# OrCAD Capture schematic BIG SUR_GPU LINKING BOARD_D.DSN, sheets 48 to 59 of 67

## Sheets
48 P49  P12V_1 Hot Swap-2: size C
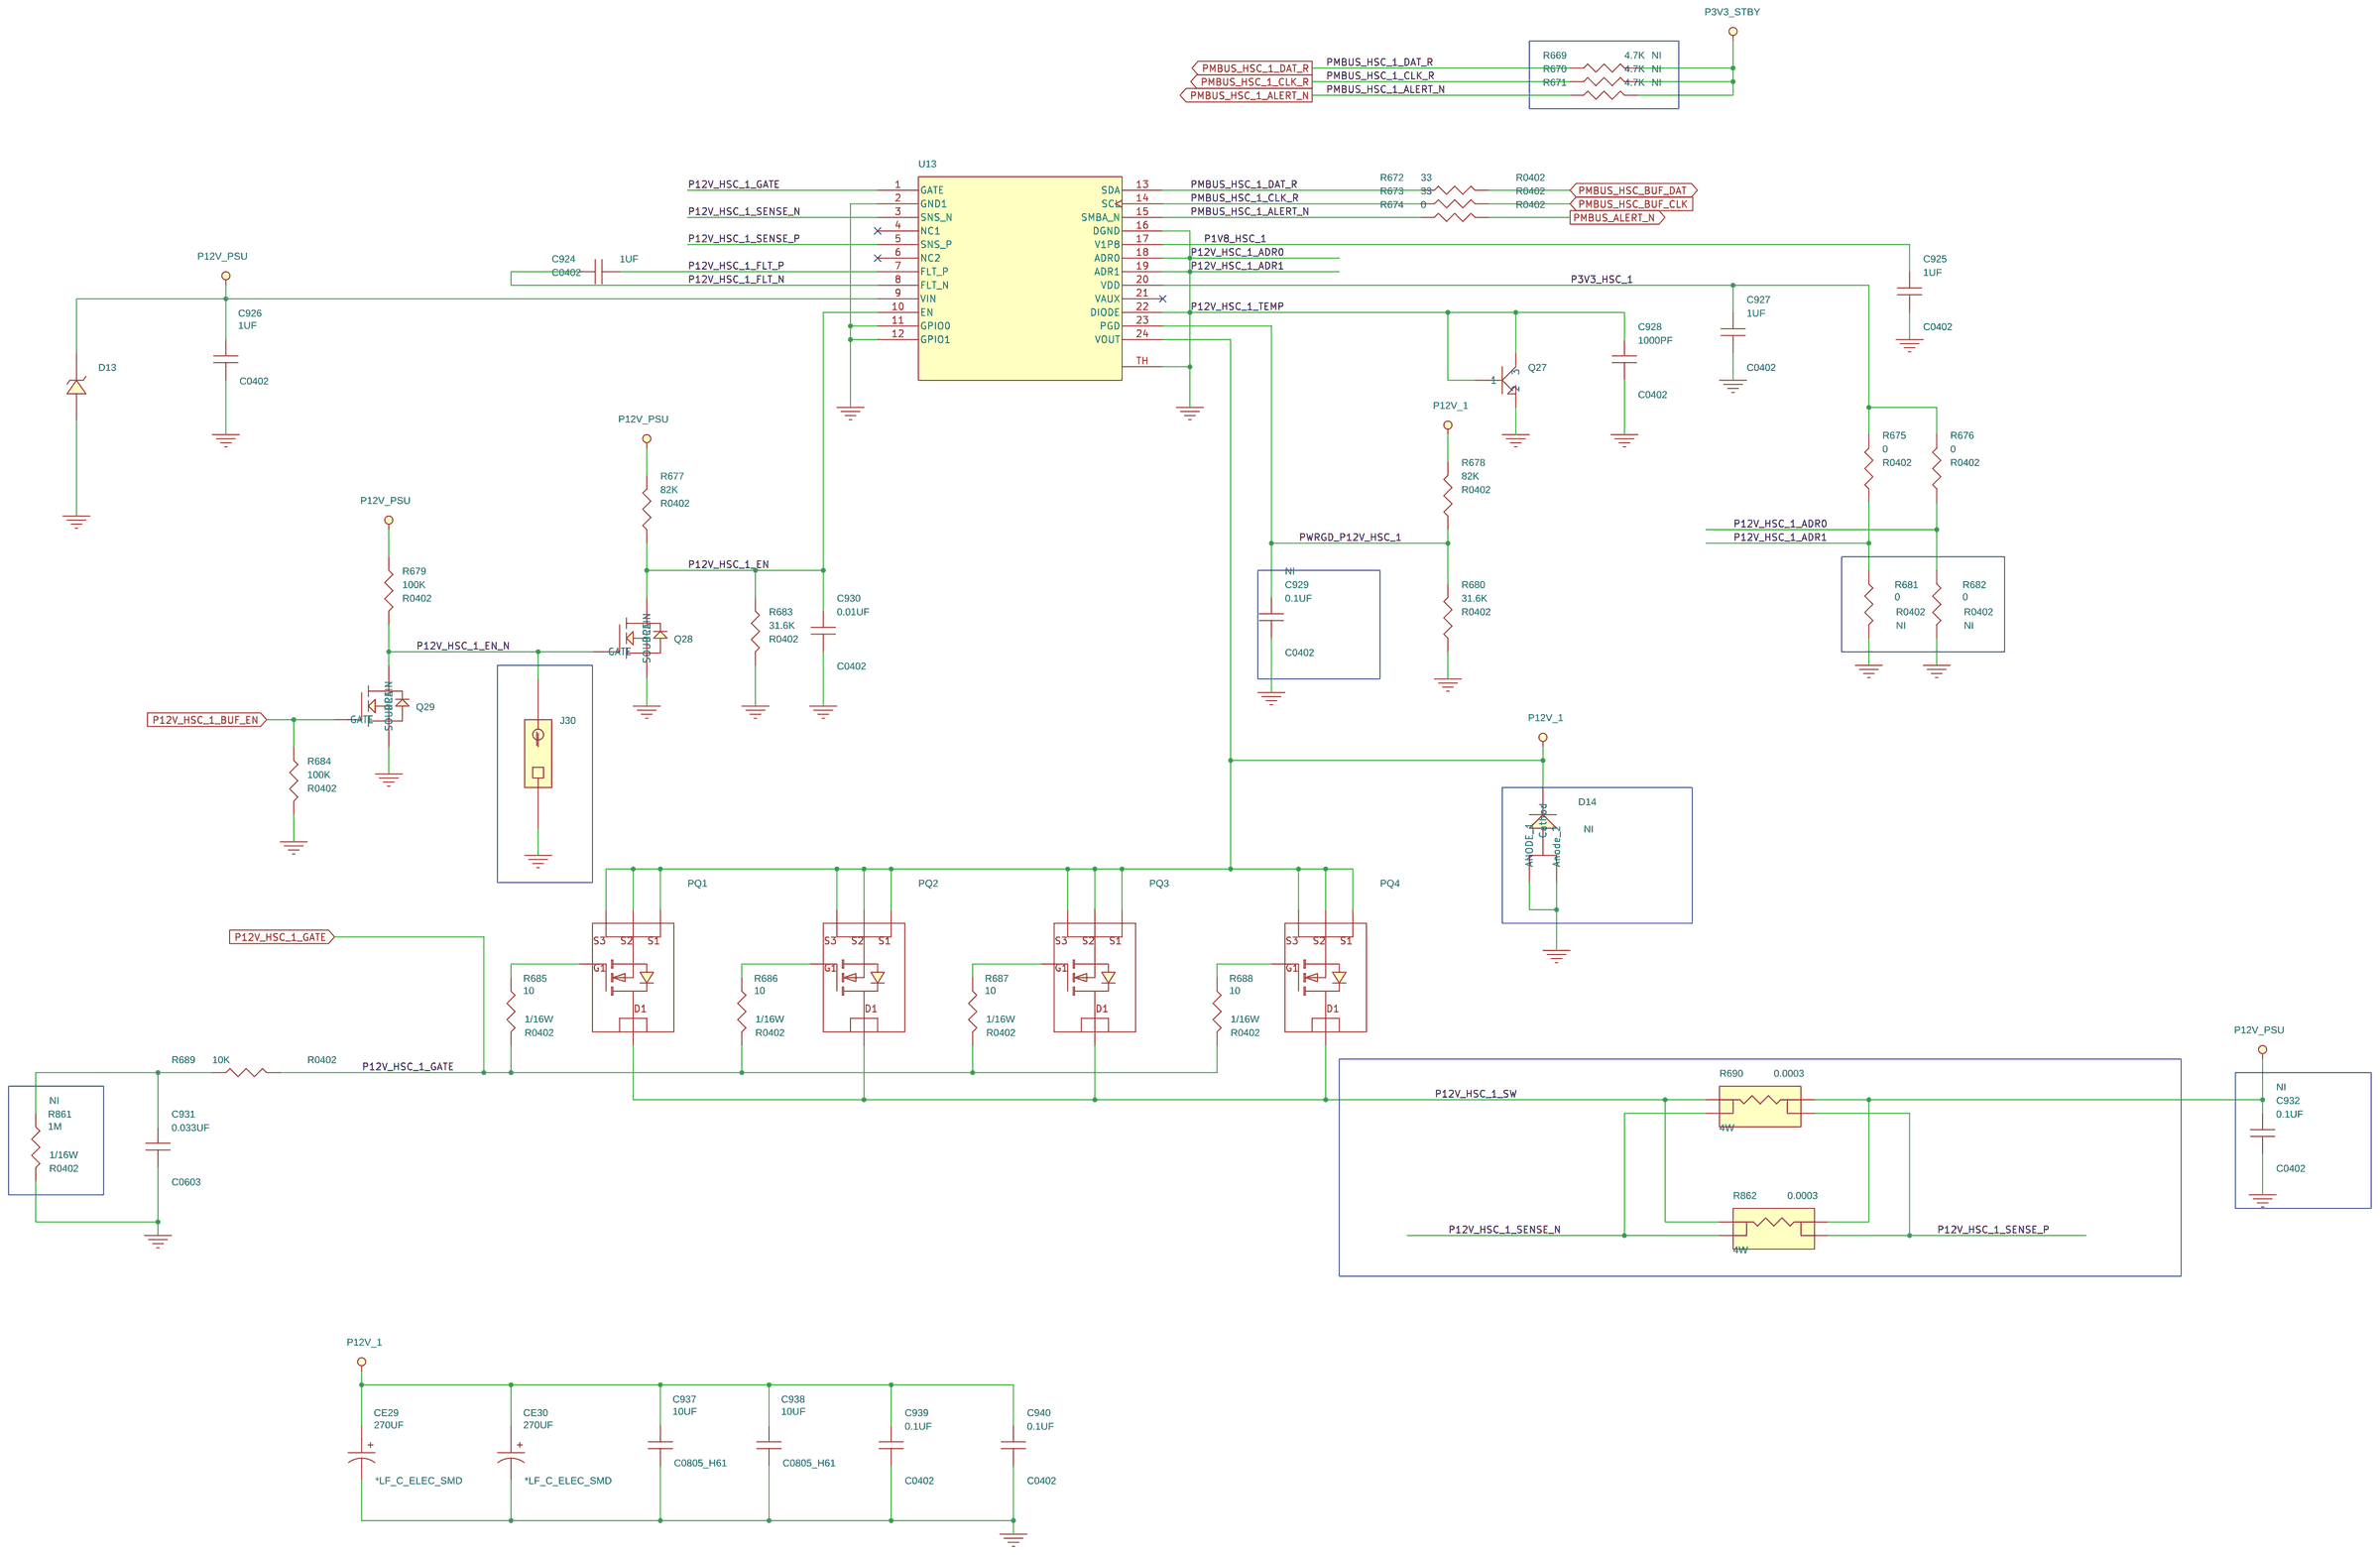
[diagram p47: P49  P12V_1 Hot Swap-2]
49 P50  P12V_2 Hot Swap-0: size C
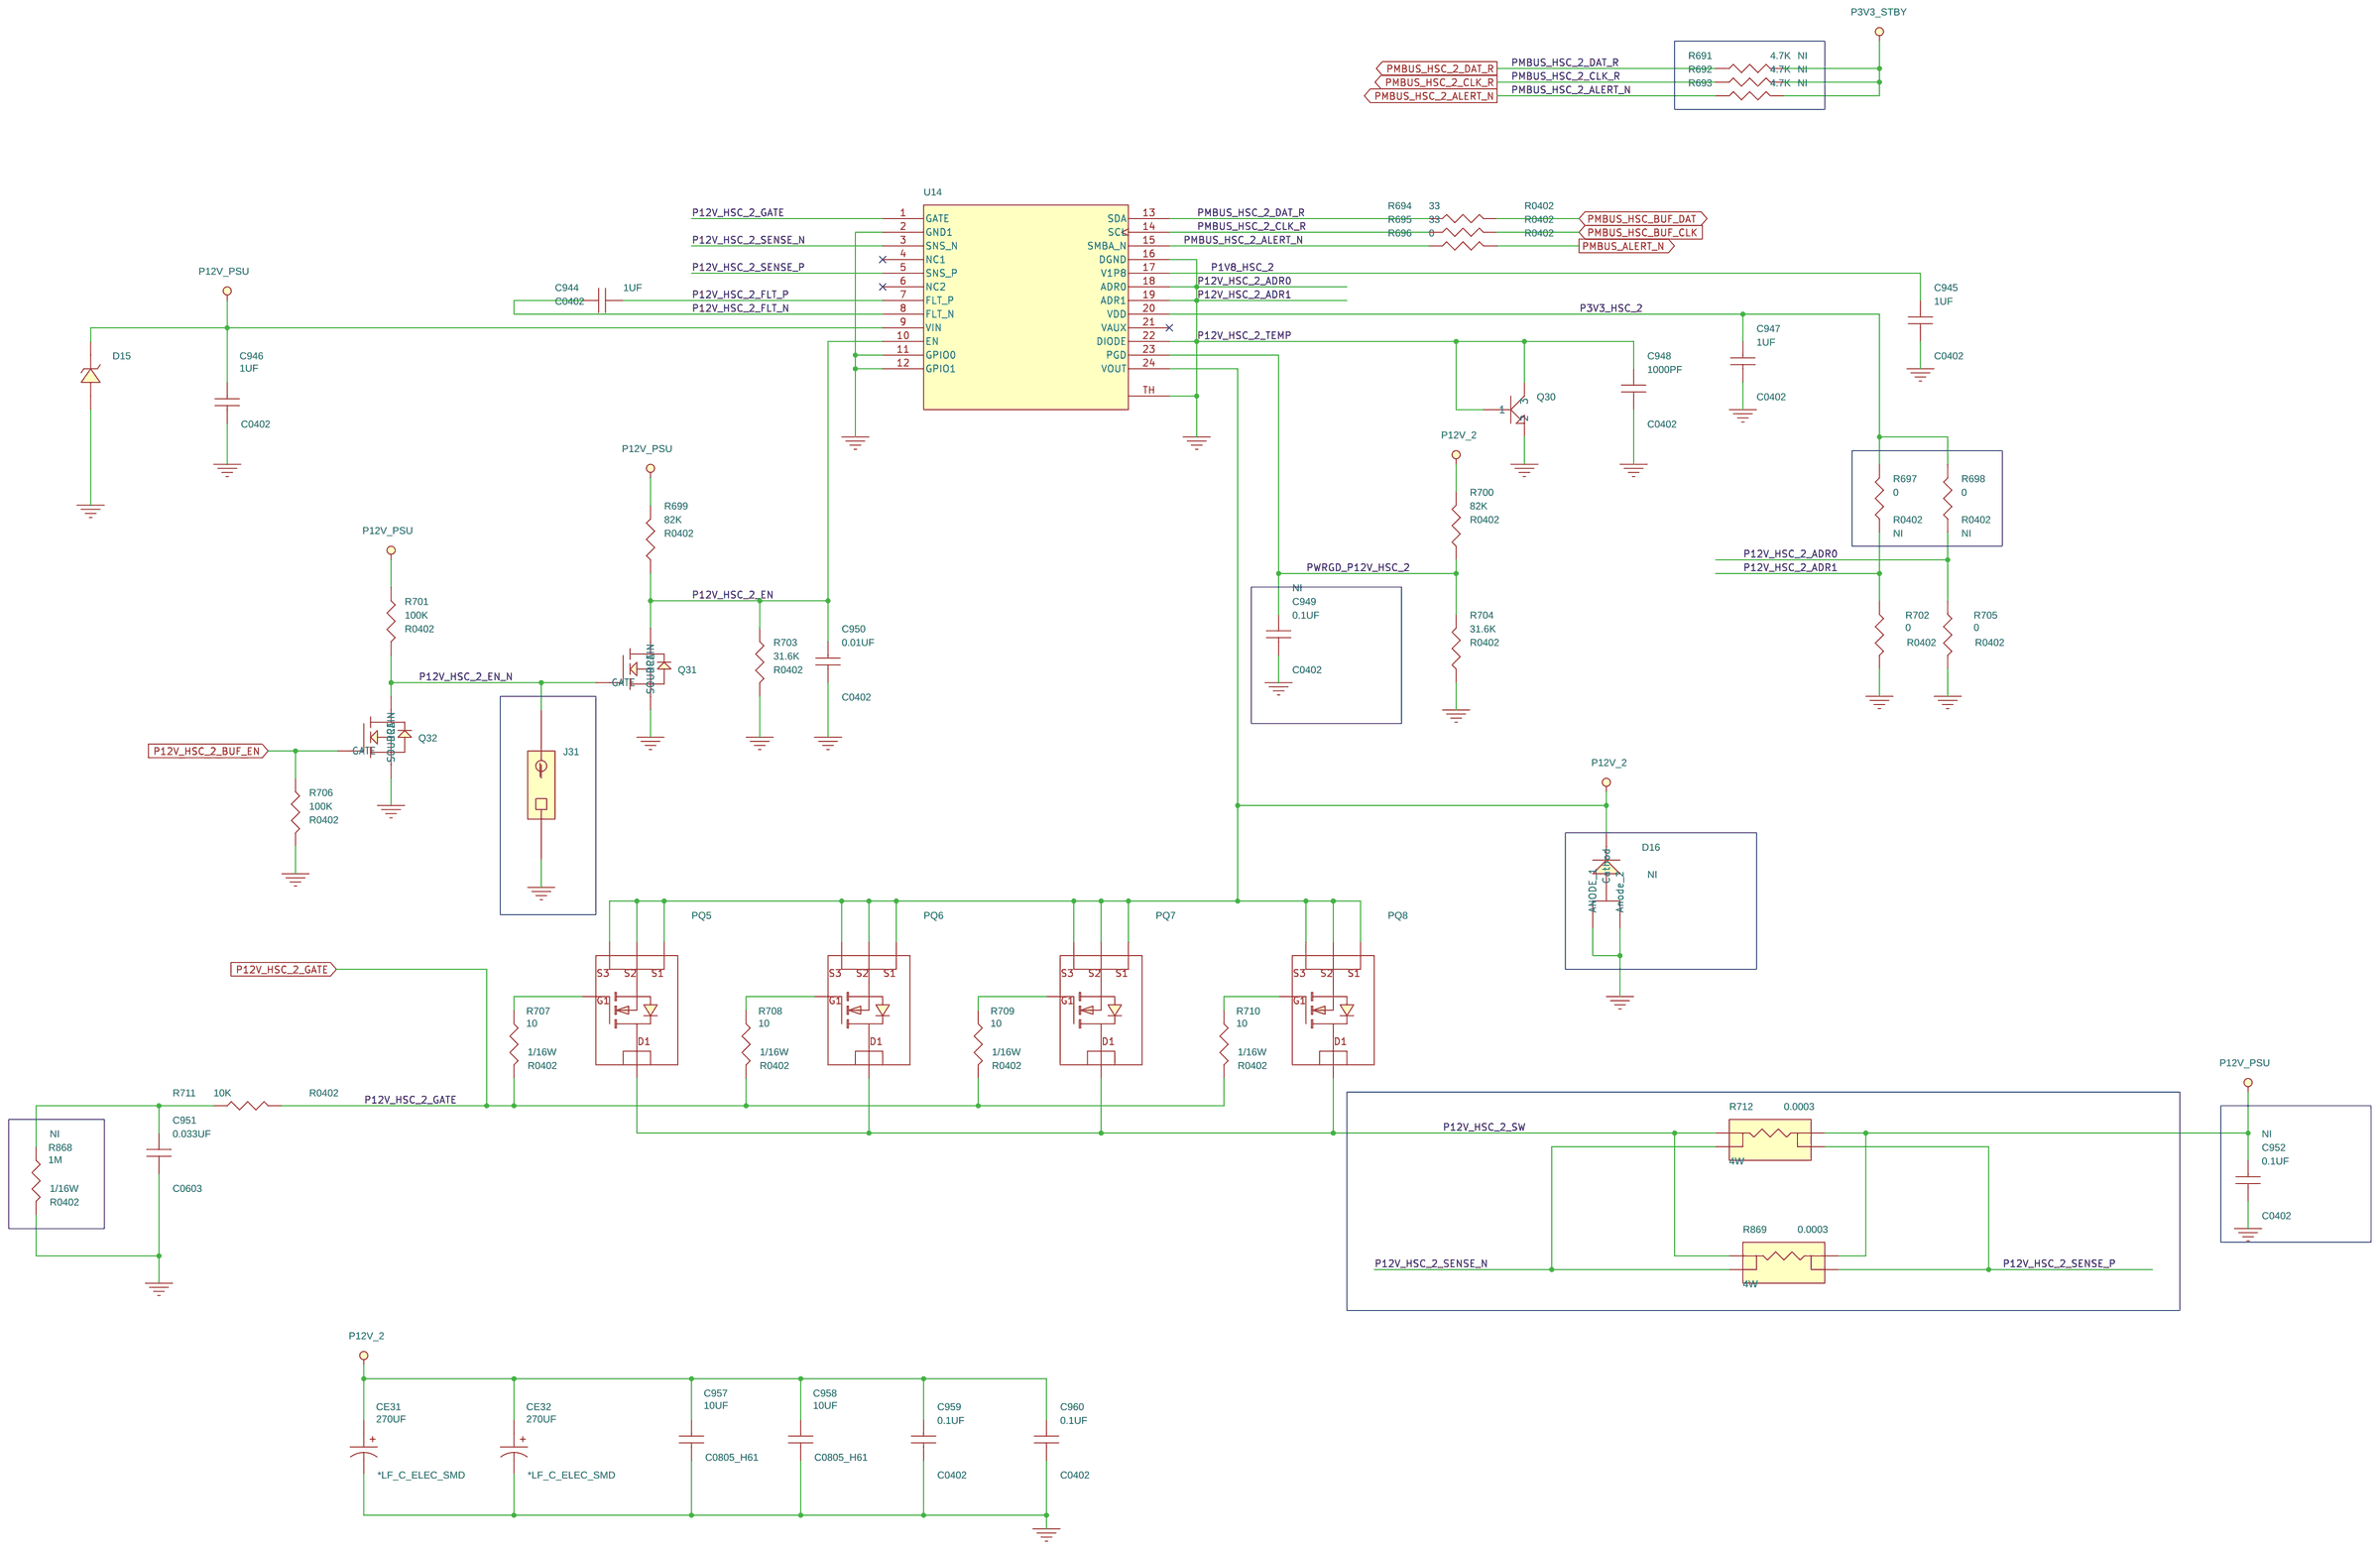
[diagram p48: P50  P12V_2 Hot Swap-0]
50 P51  P12V Hot Swap-1: size C
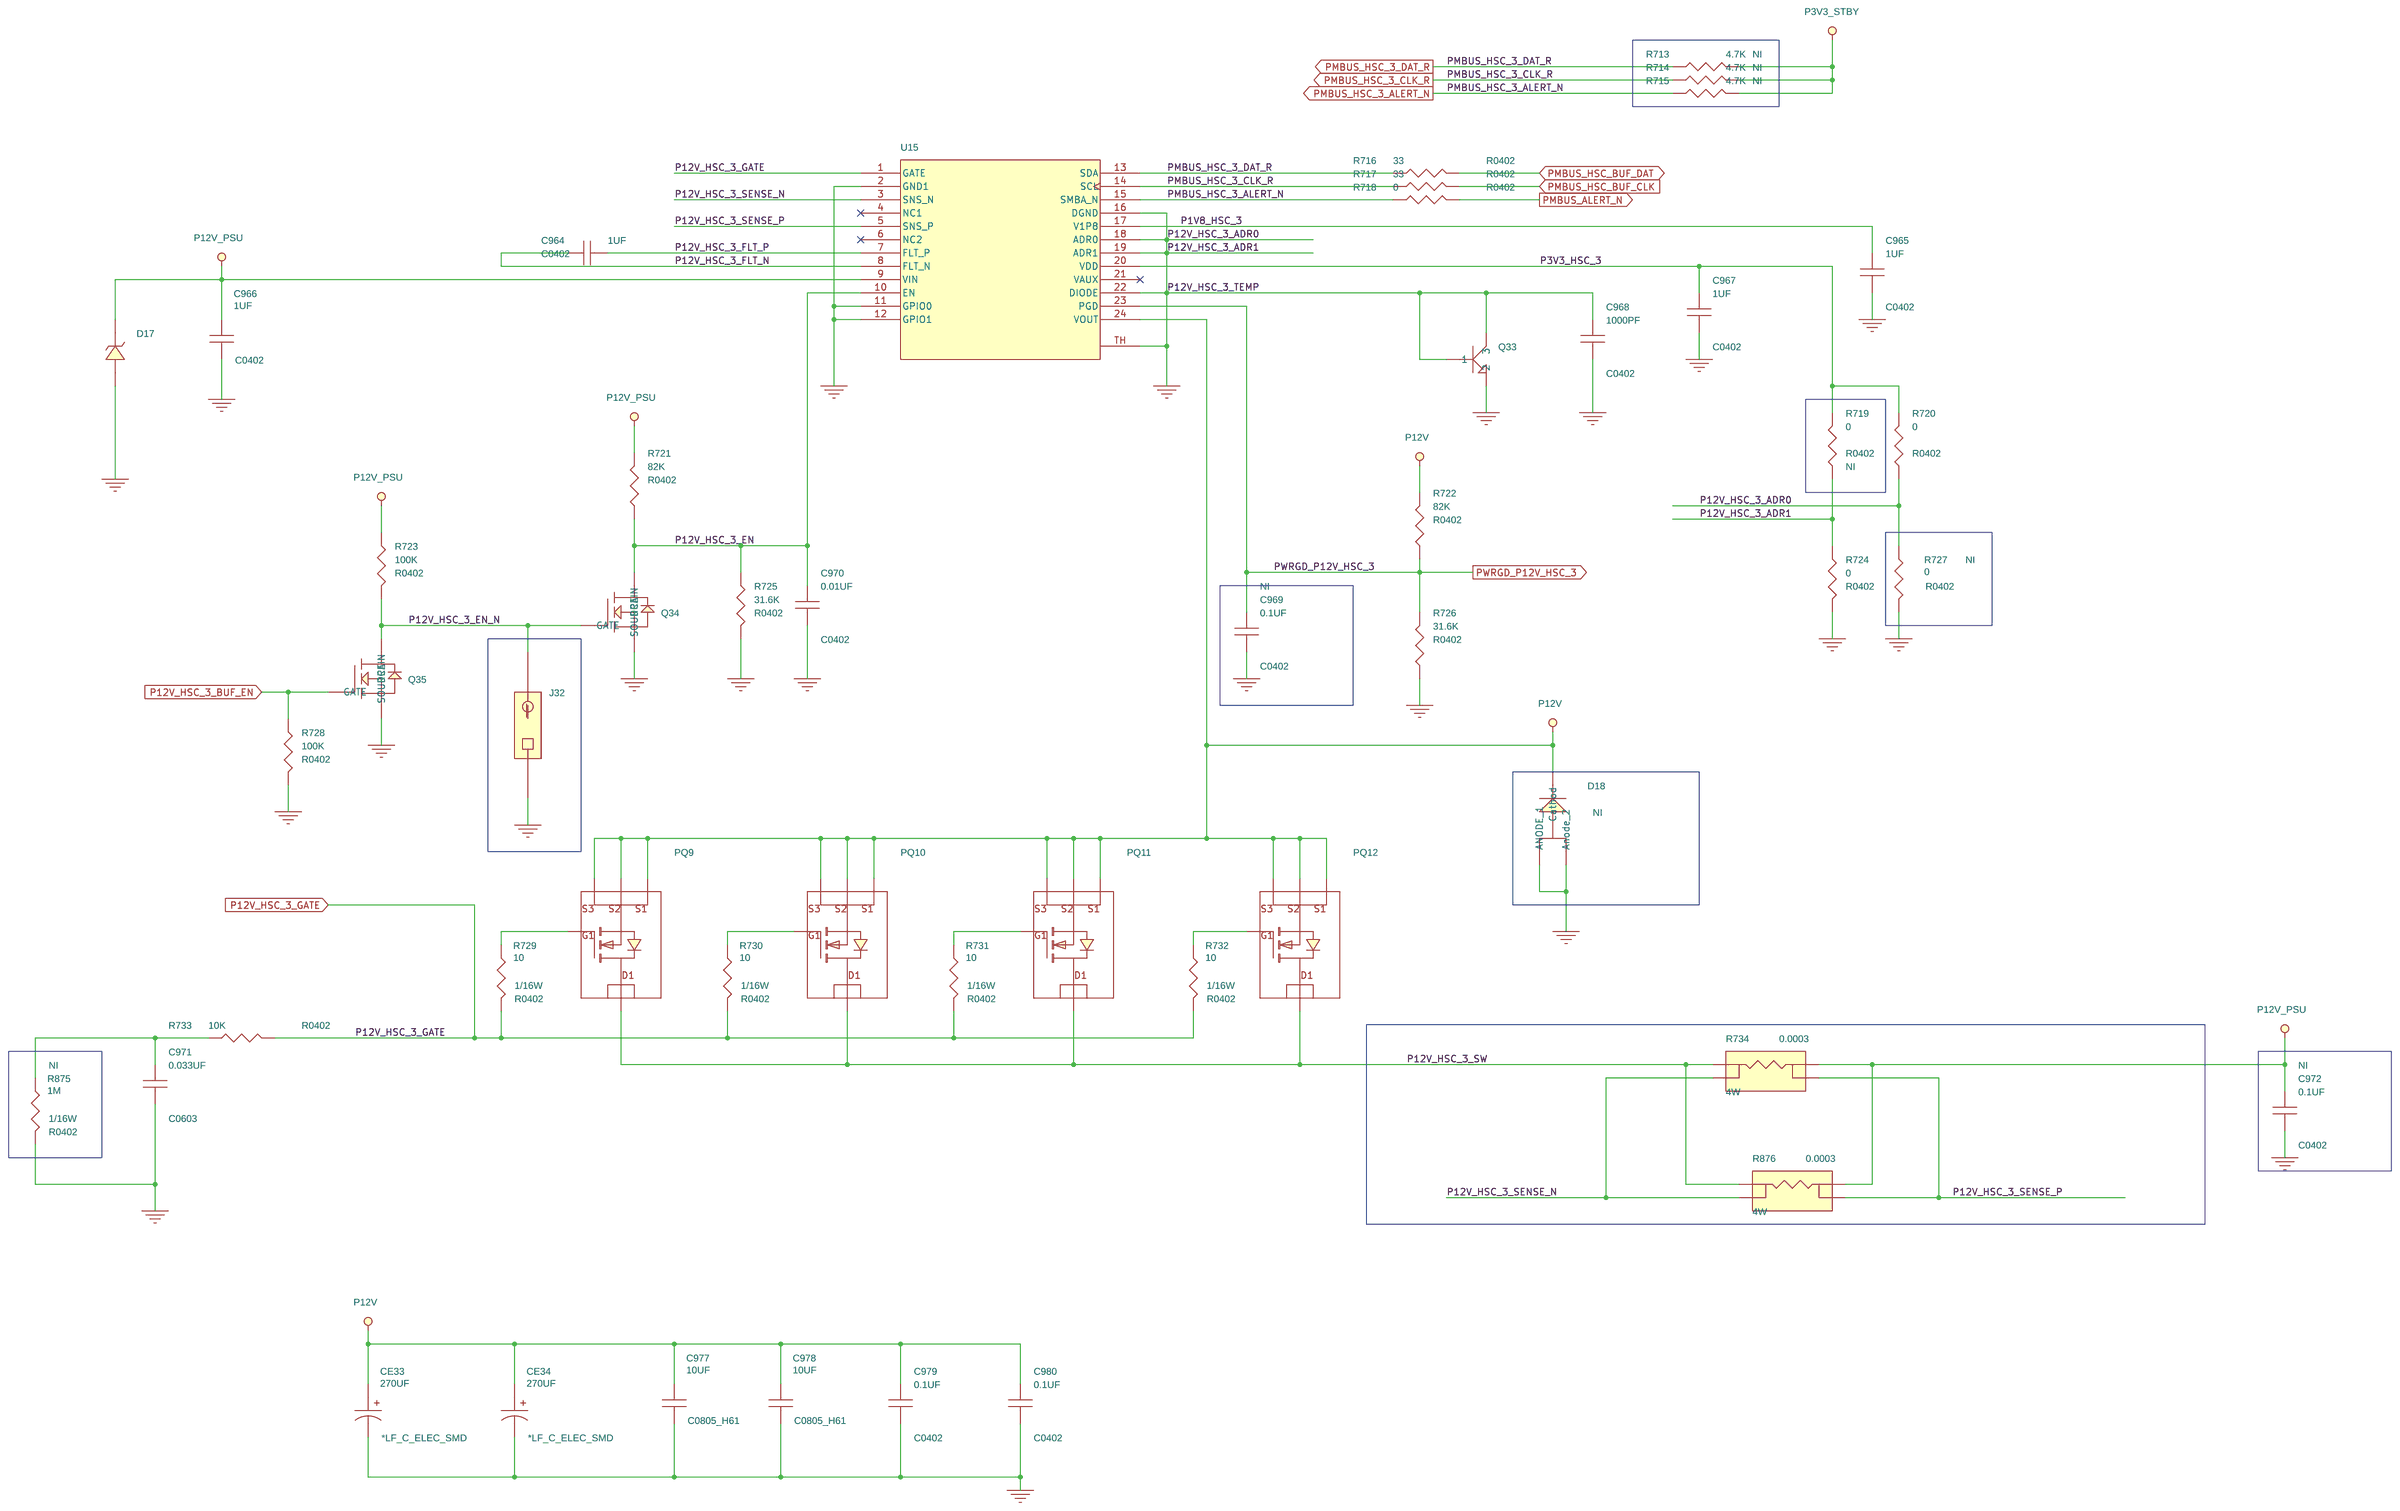
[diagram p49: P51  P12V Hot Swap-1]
51 P52  Hardware Monitor: size C
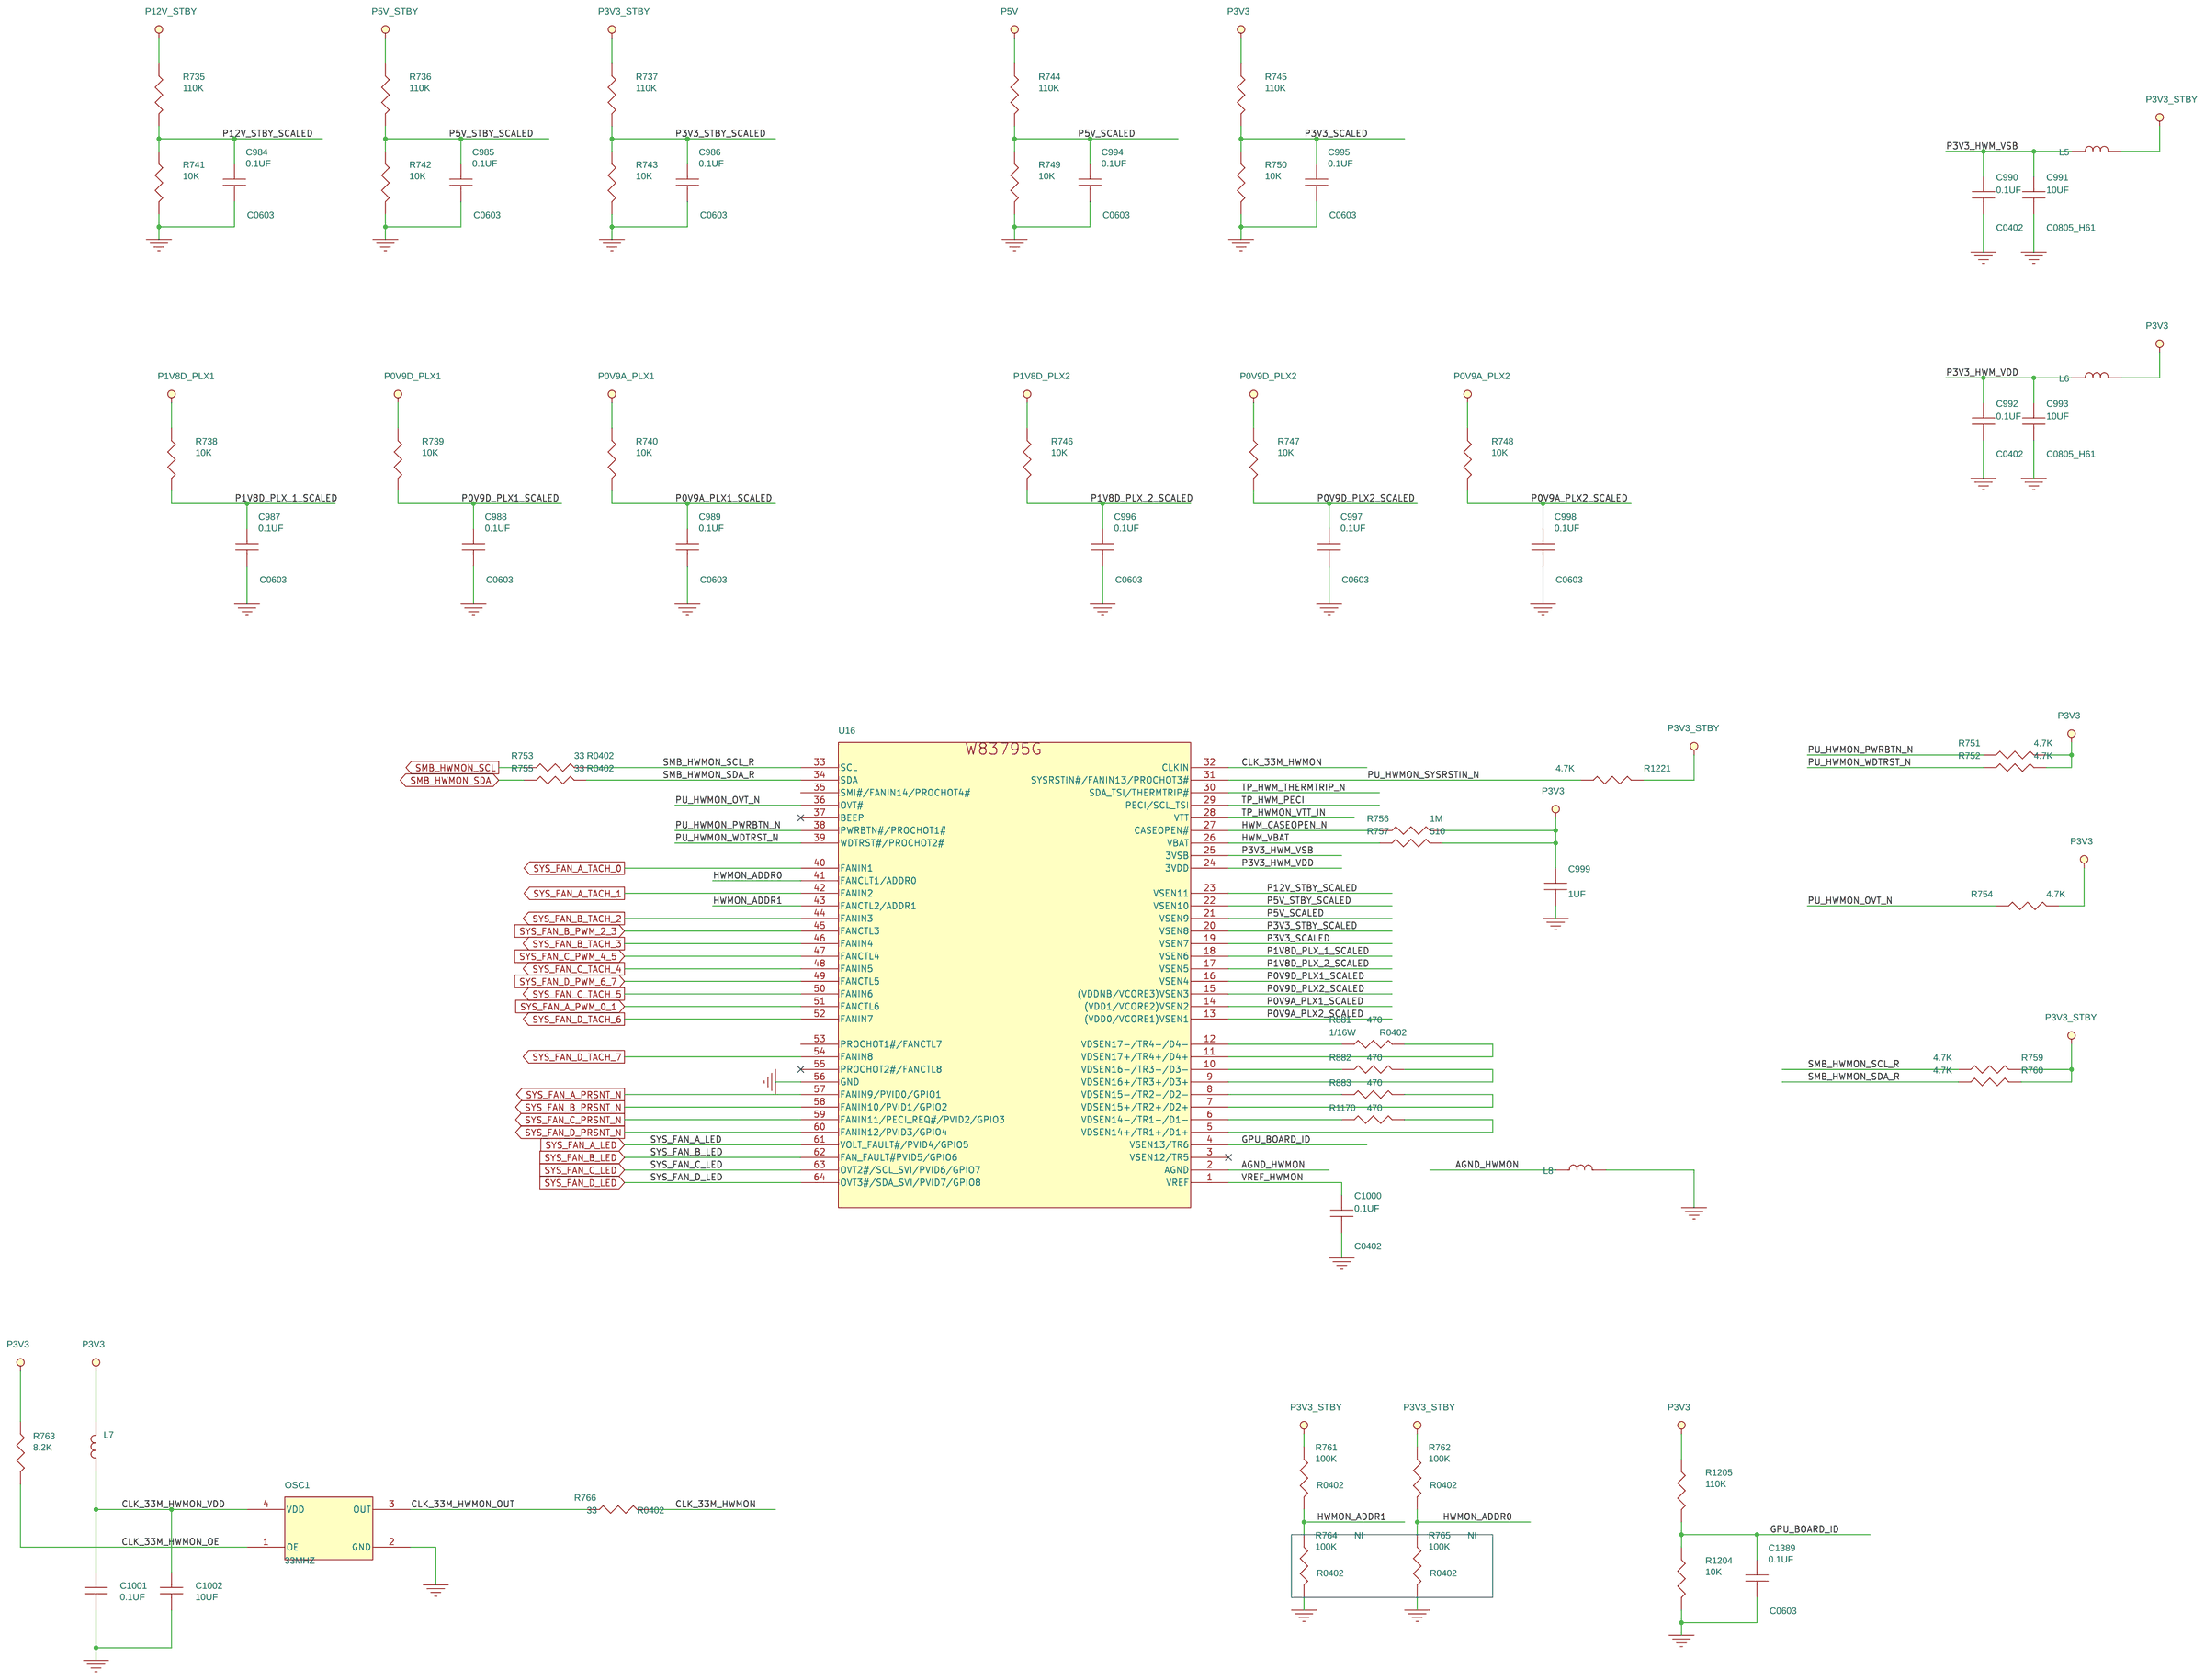
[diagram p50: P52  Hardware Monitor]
52 P53 Sytem Fan Module Connector: size C
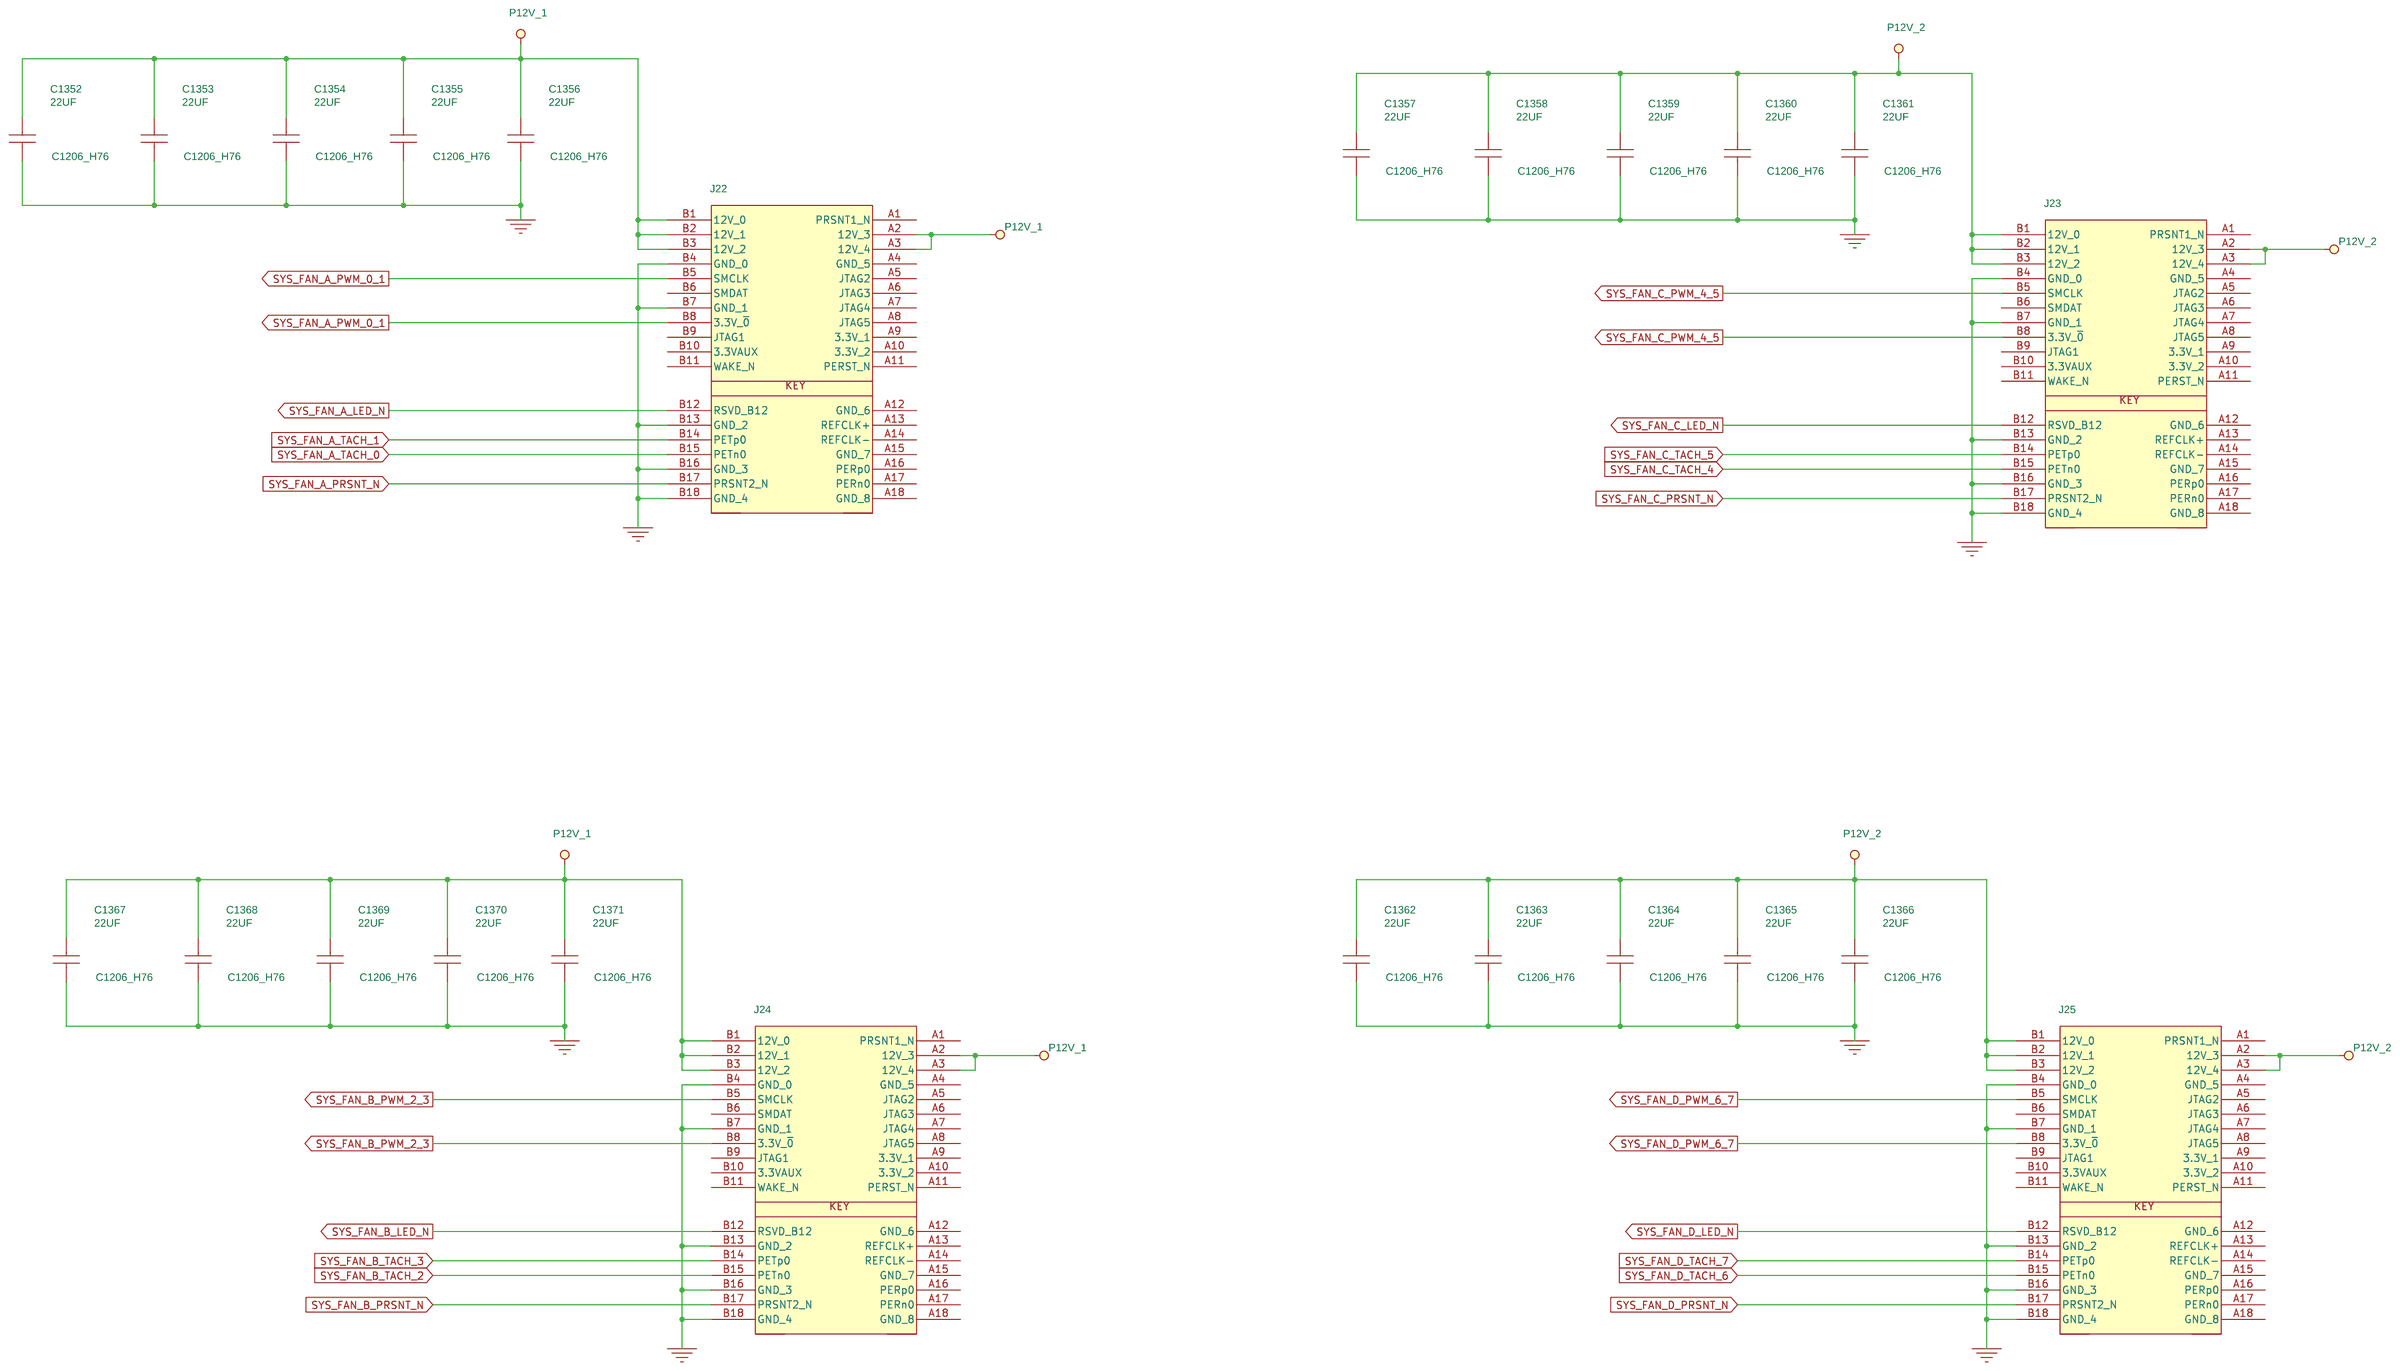
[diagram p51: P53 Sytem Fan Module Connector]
53 P54  Sytem Fan Module: size C
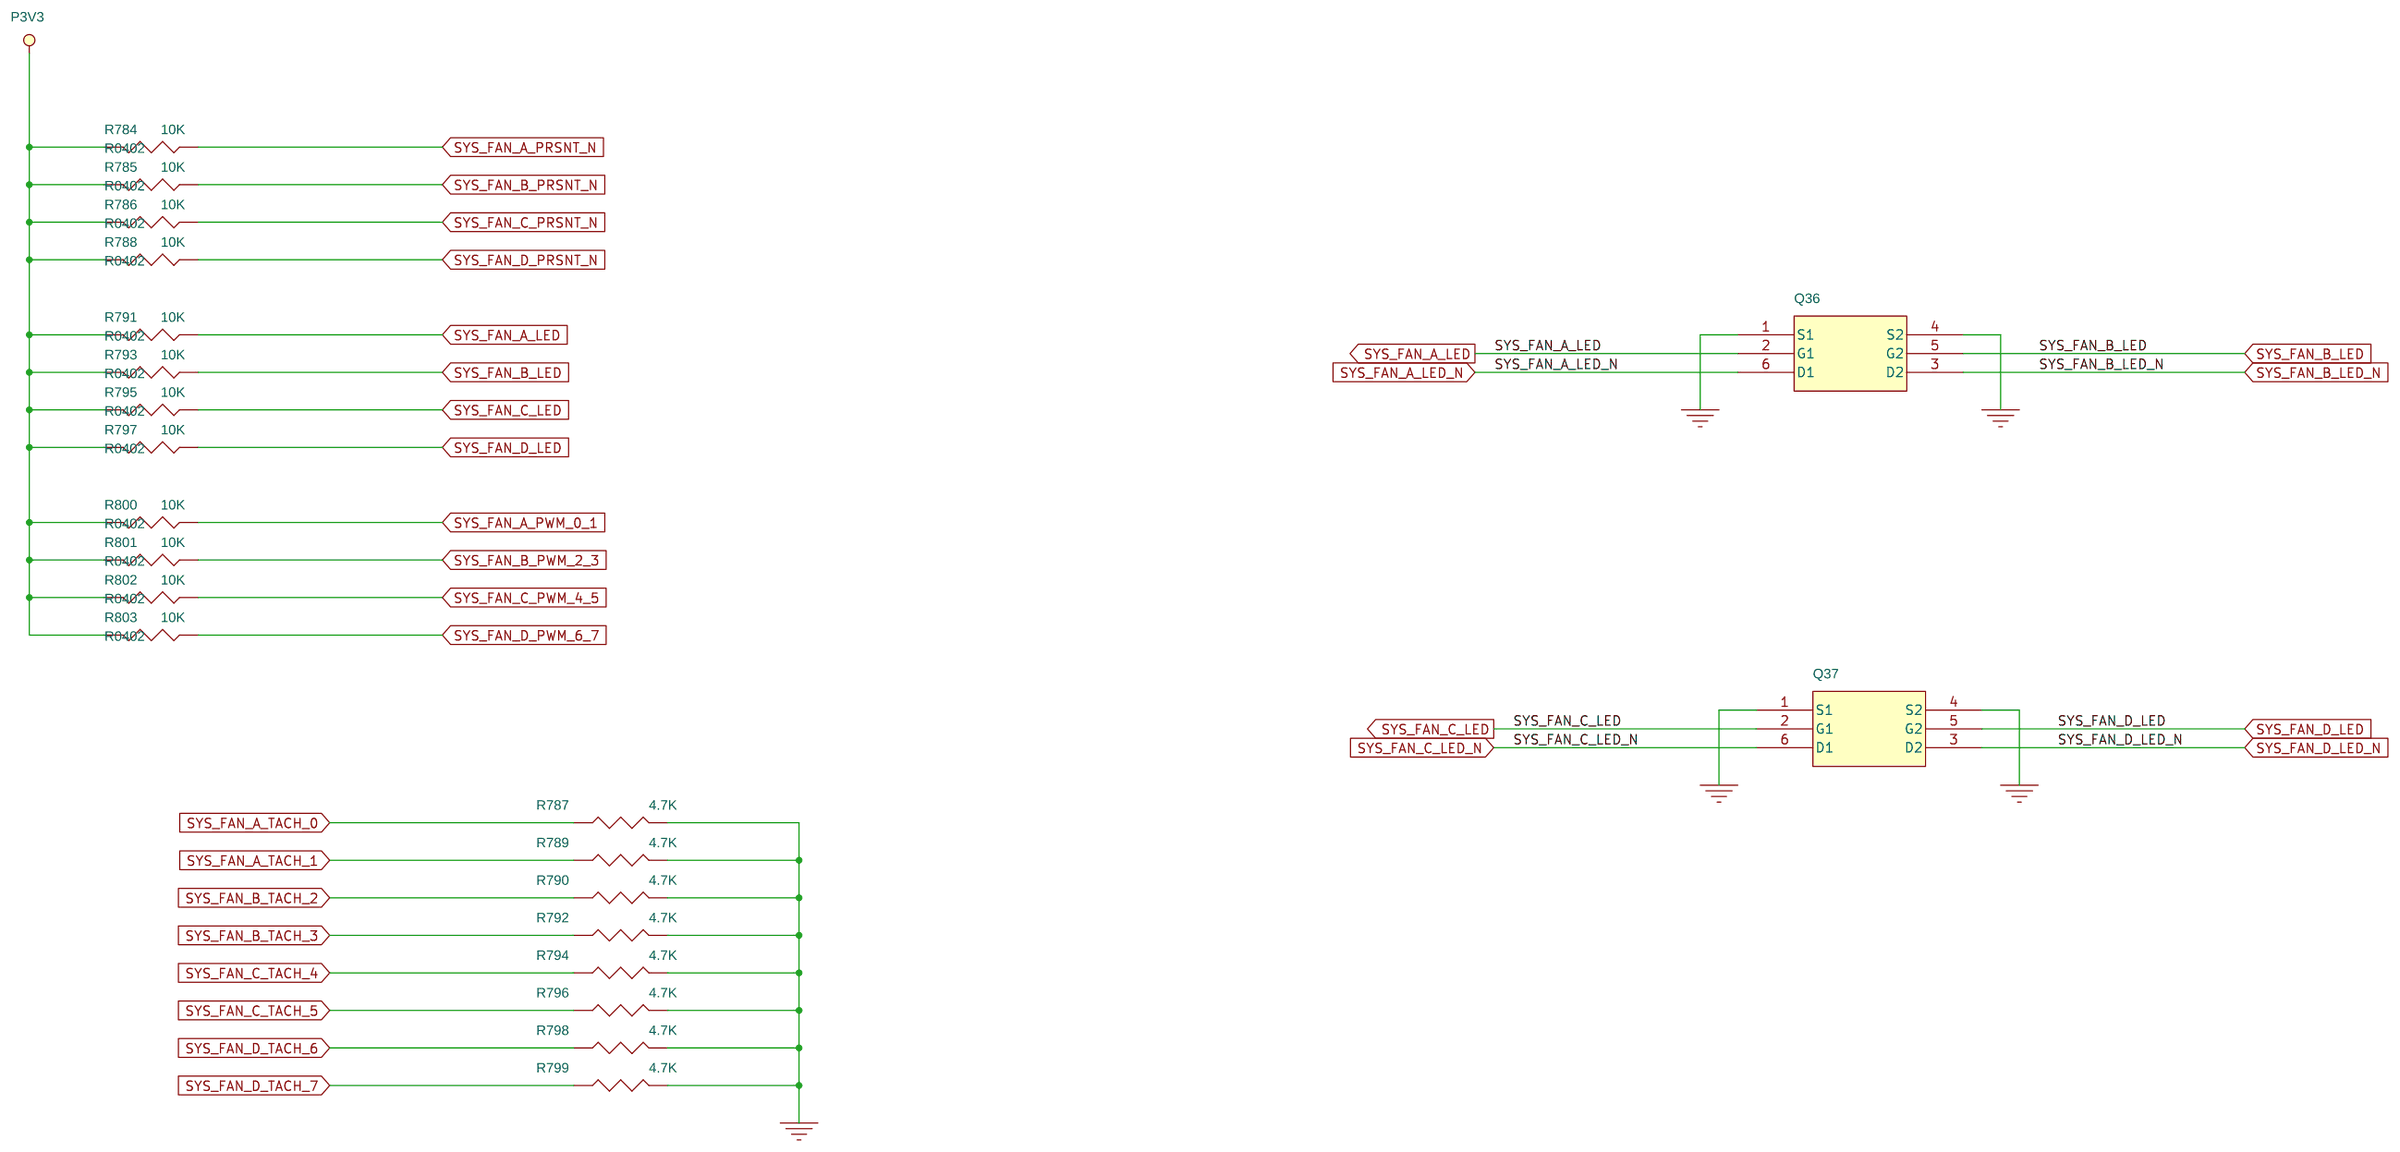
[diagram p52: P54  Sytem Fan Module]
54 P56  Reset Control Circuit-1: size Custom
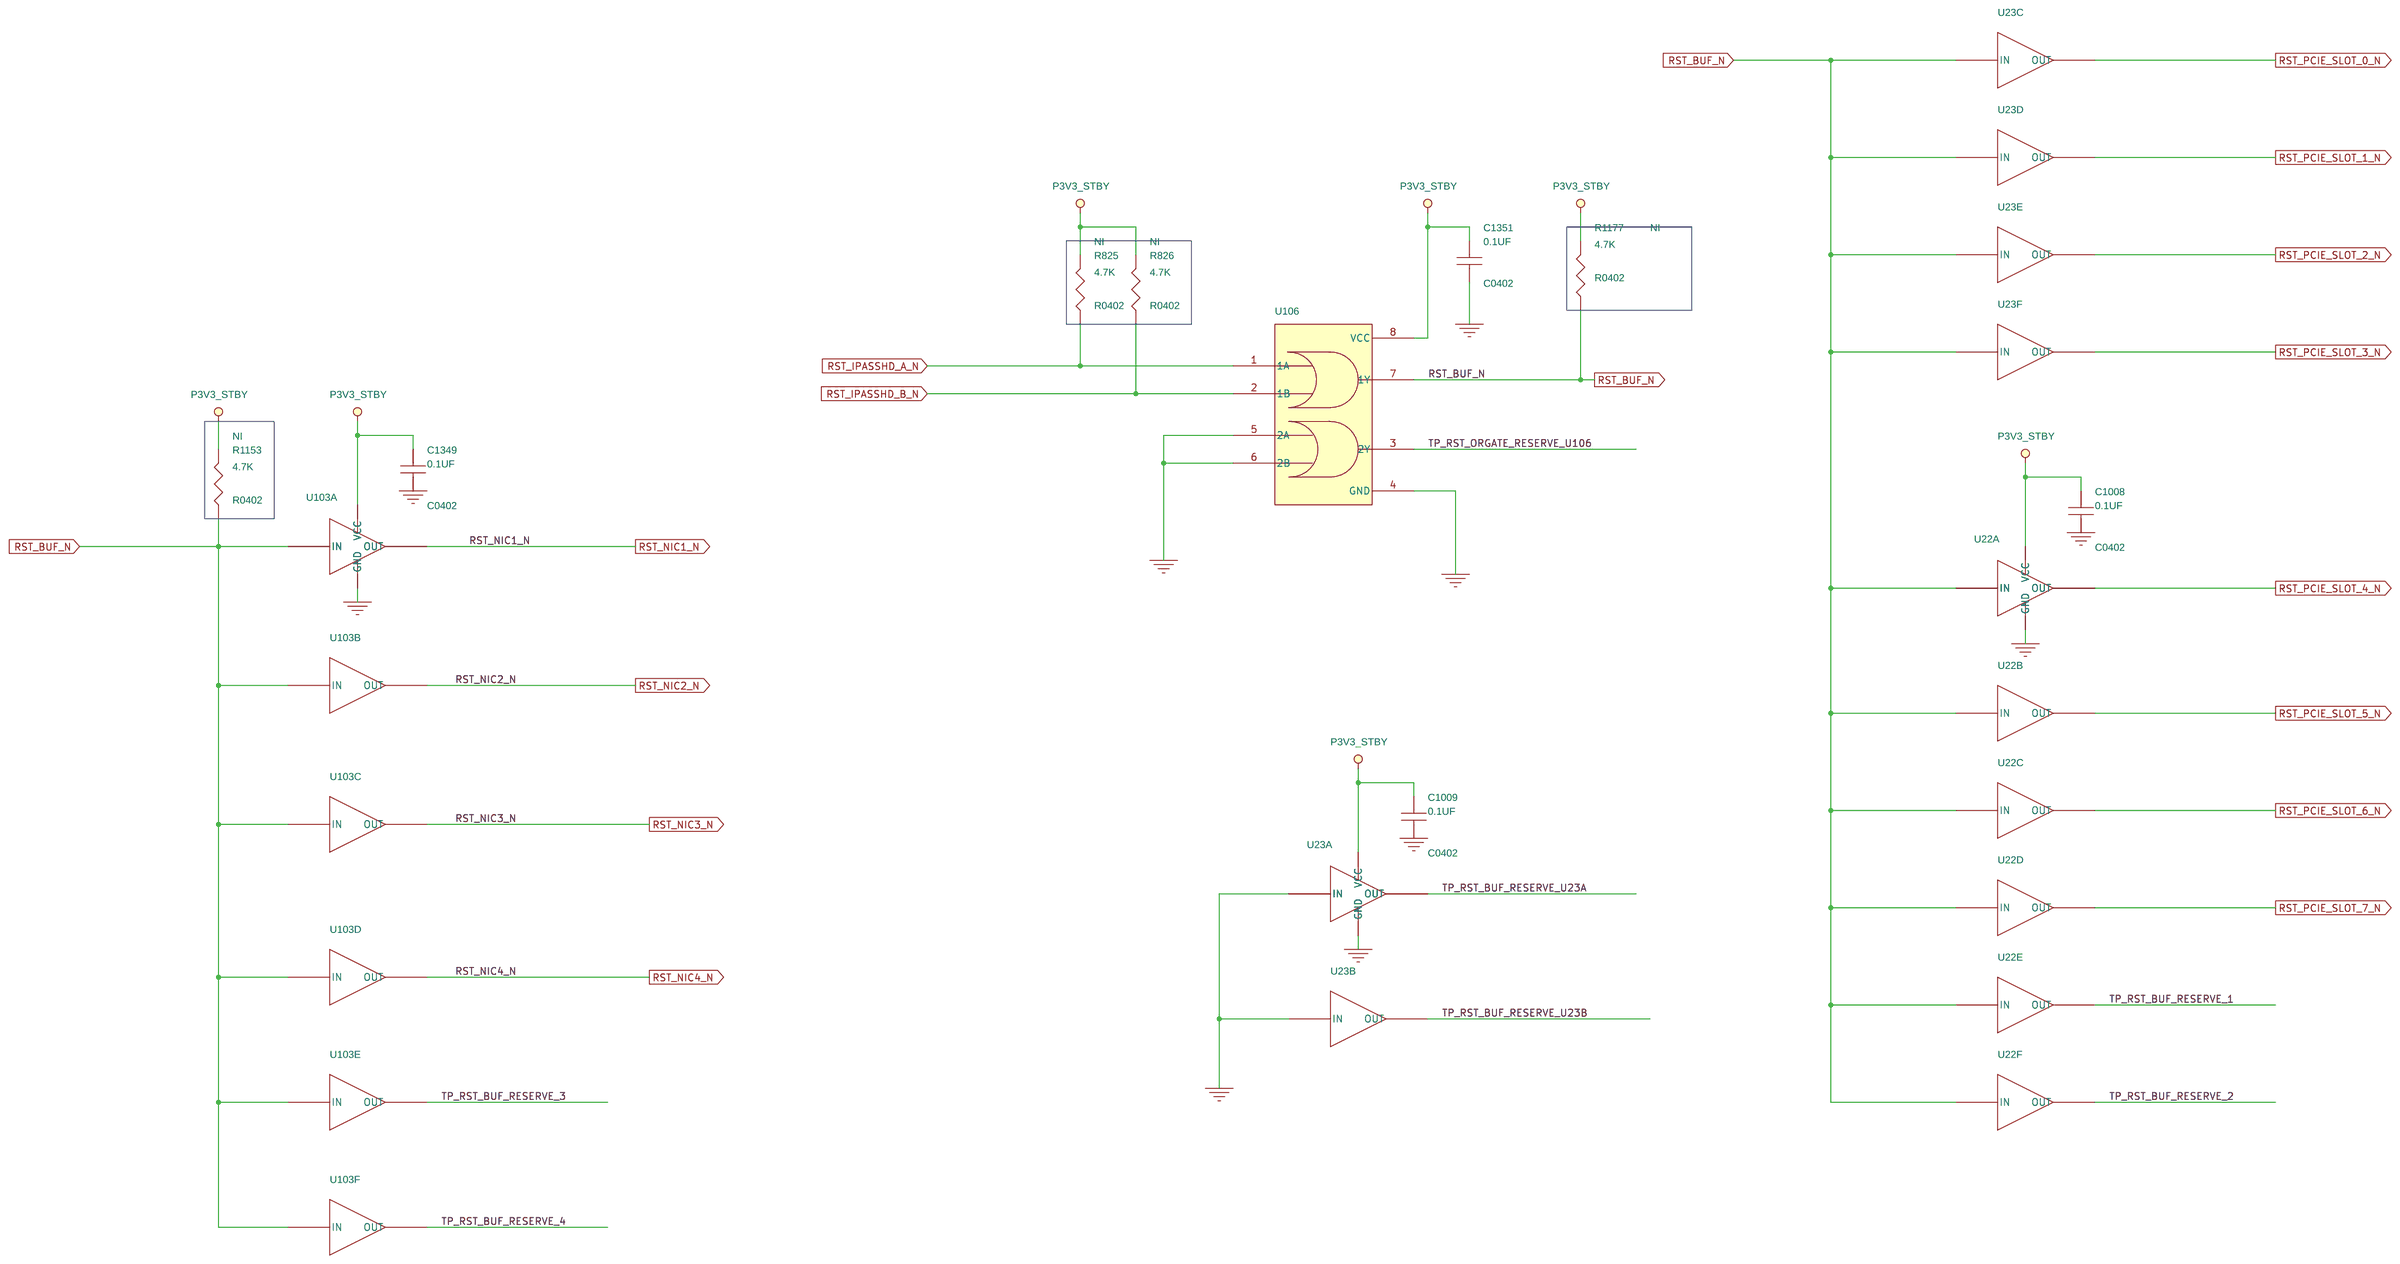
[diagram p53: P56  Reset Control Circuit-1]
55 P57  Reset Control Circuit-2: size Custom
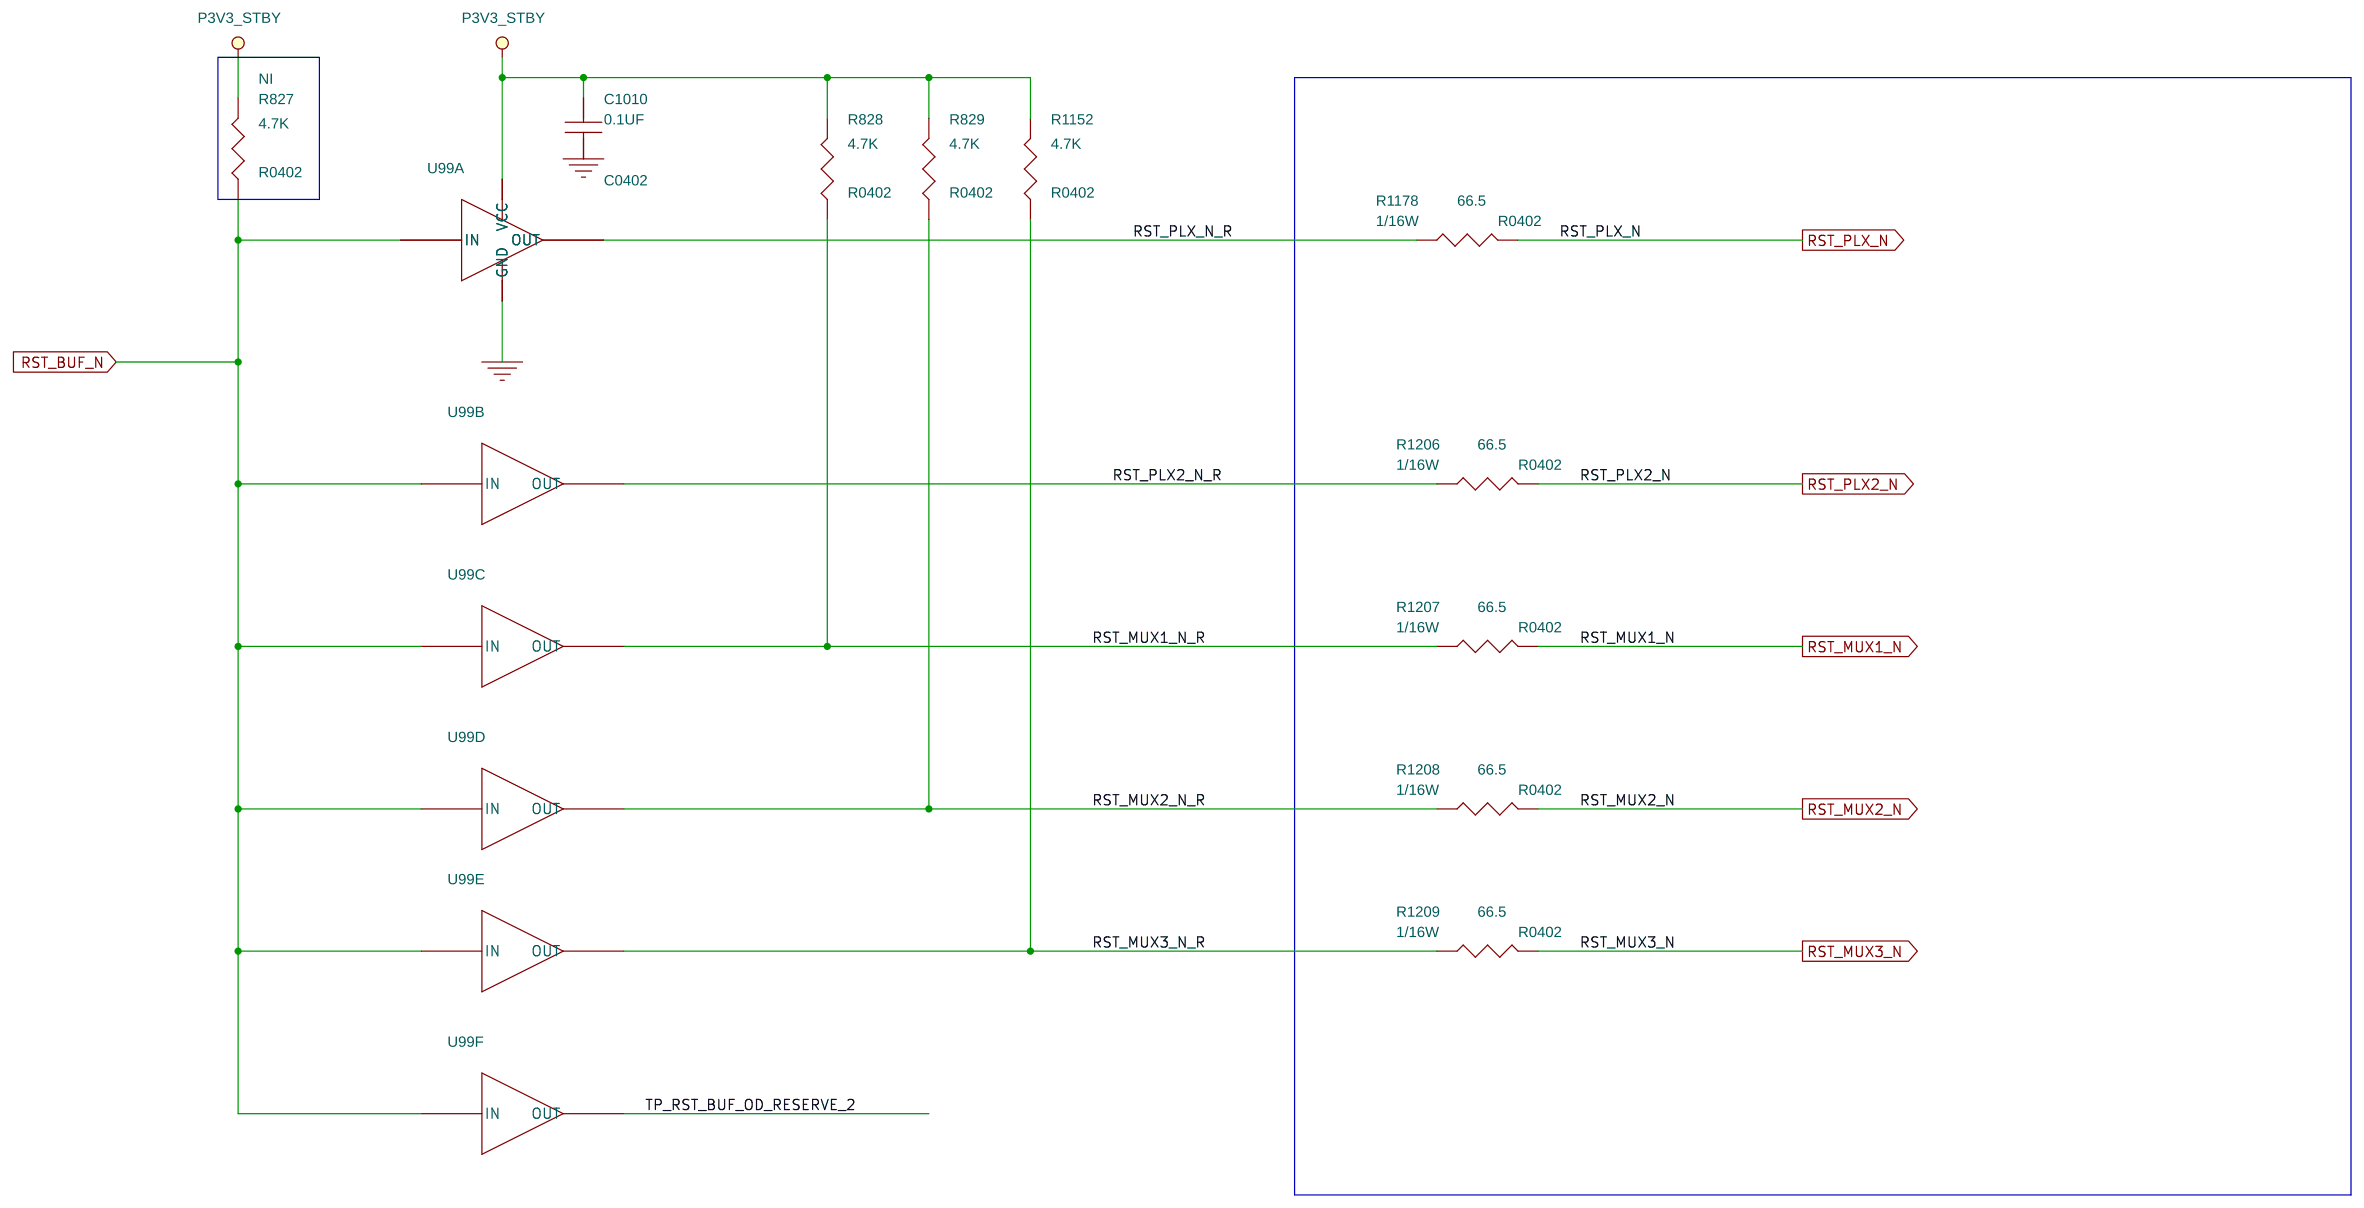
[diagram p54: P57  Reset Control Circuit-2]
56 P58  P5V_STBY VR: size Custom
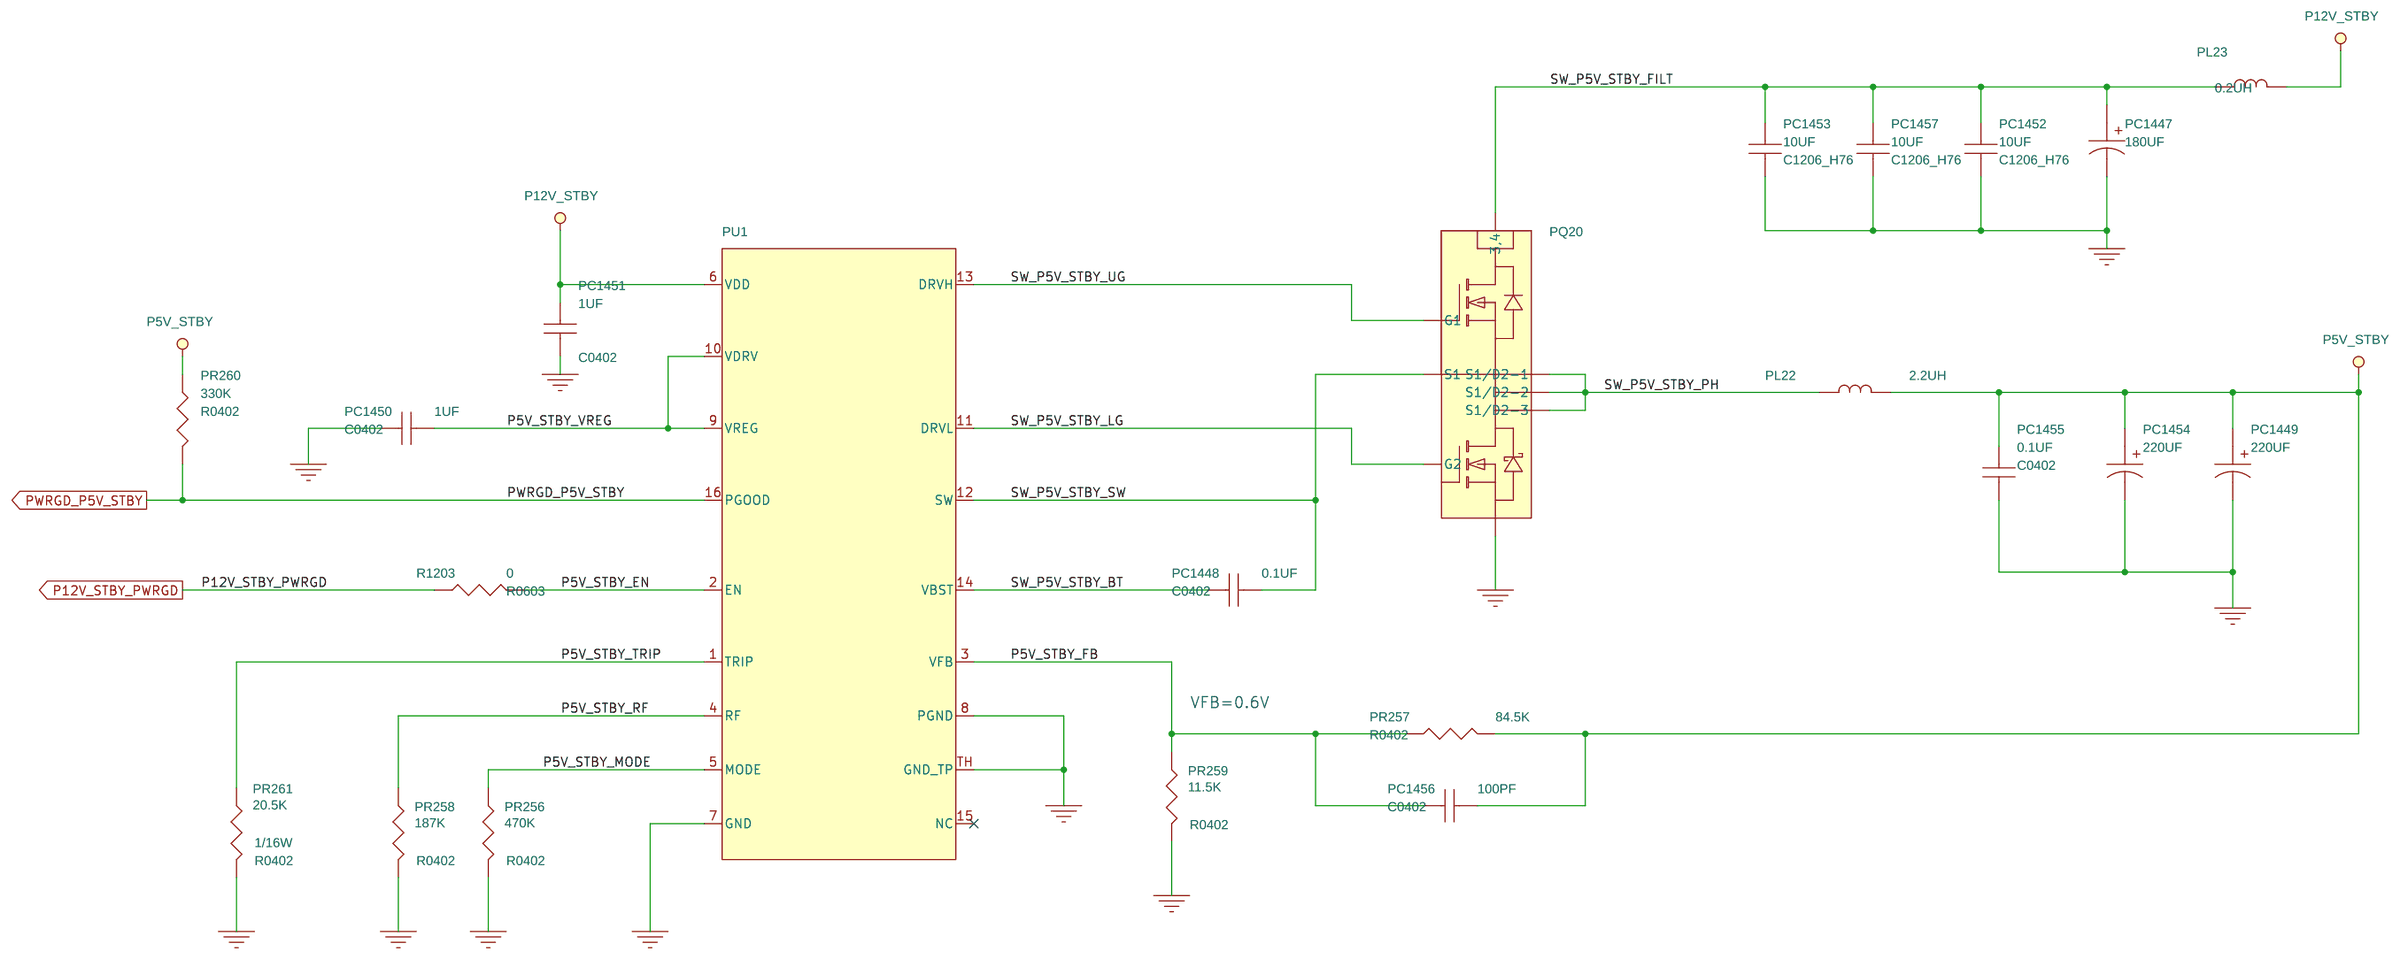
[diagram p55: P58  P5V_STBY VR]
57 P59  P5V VR: size B
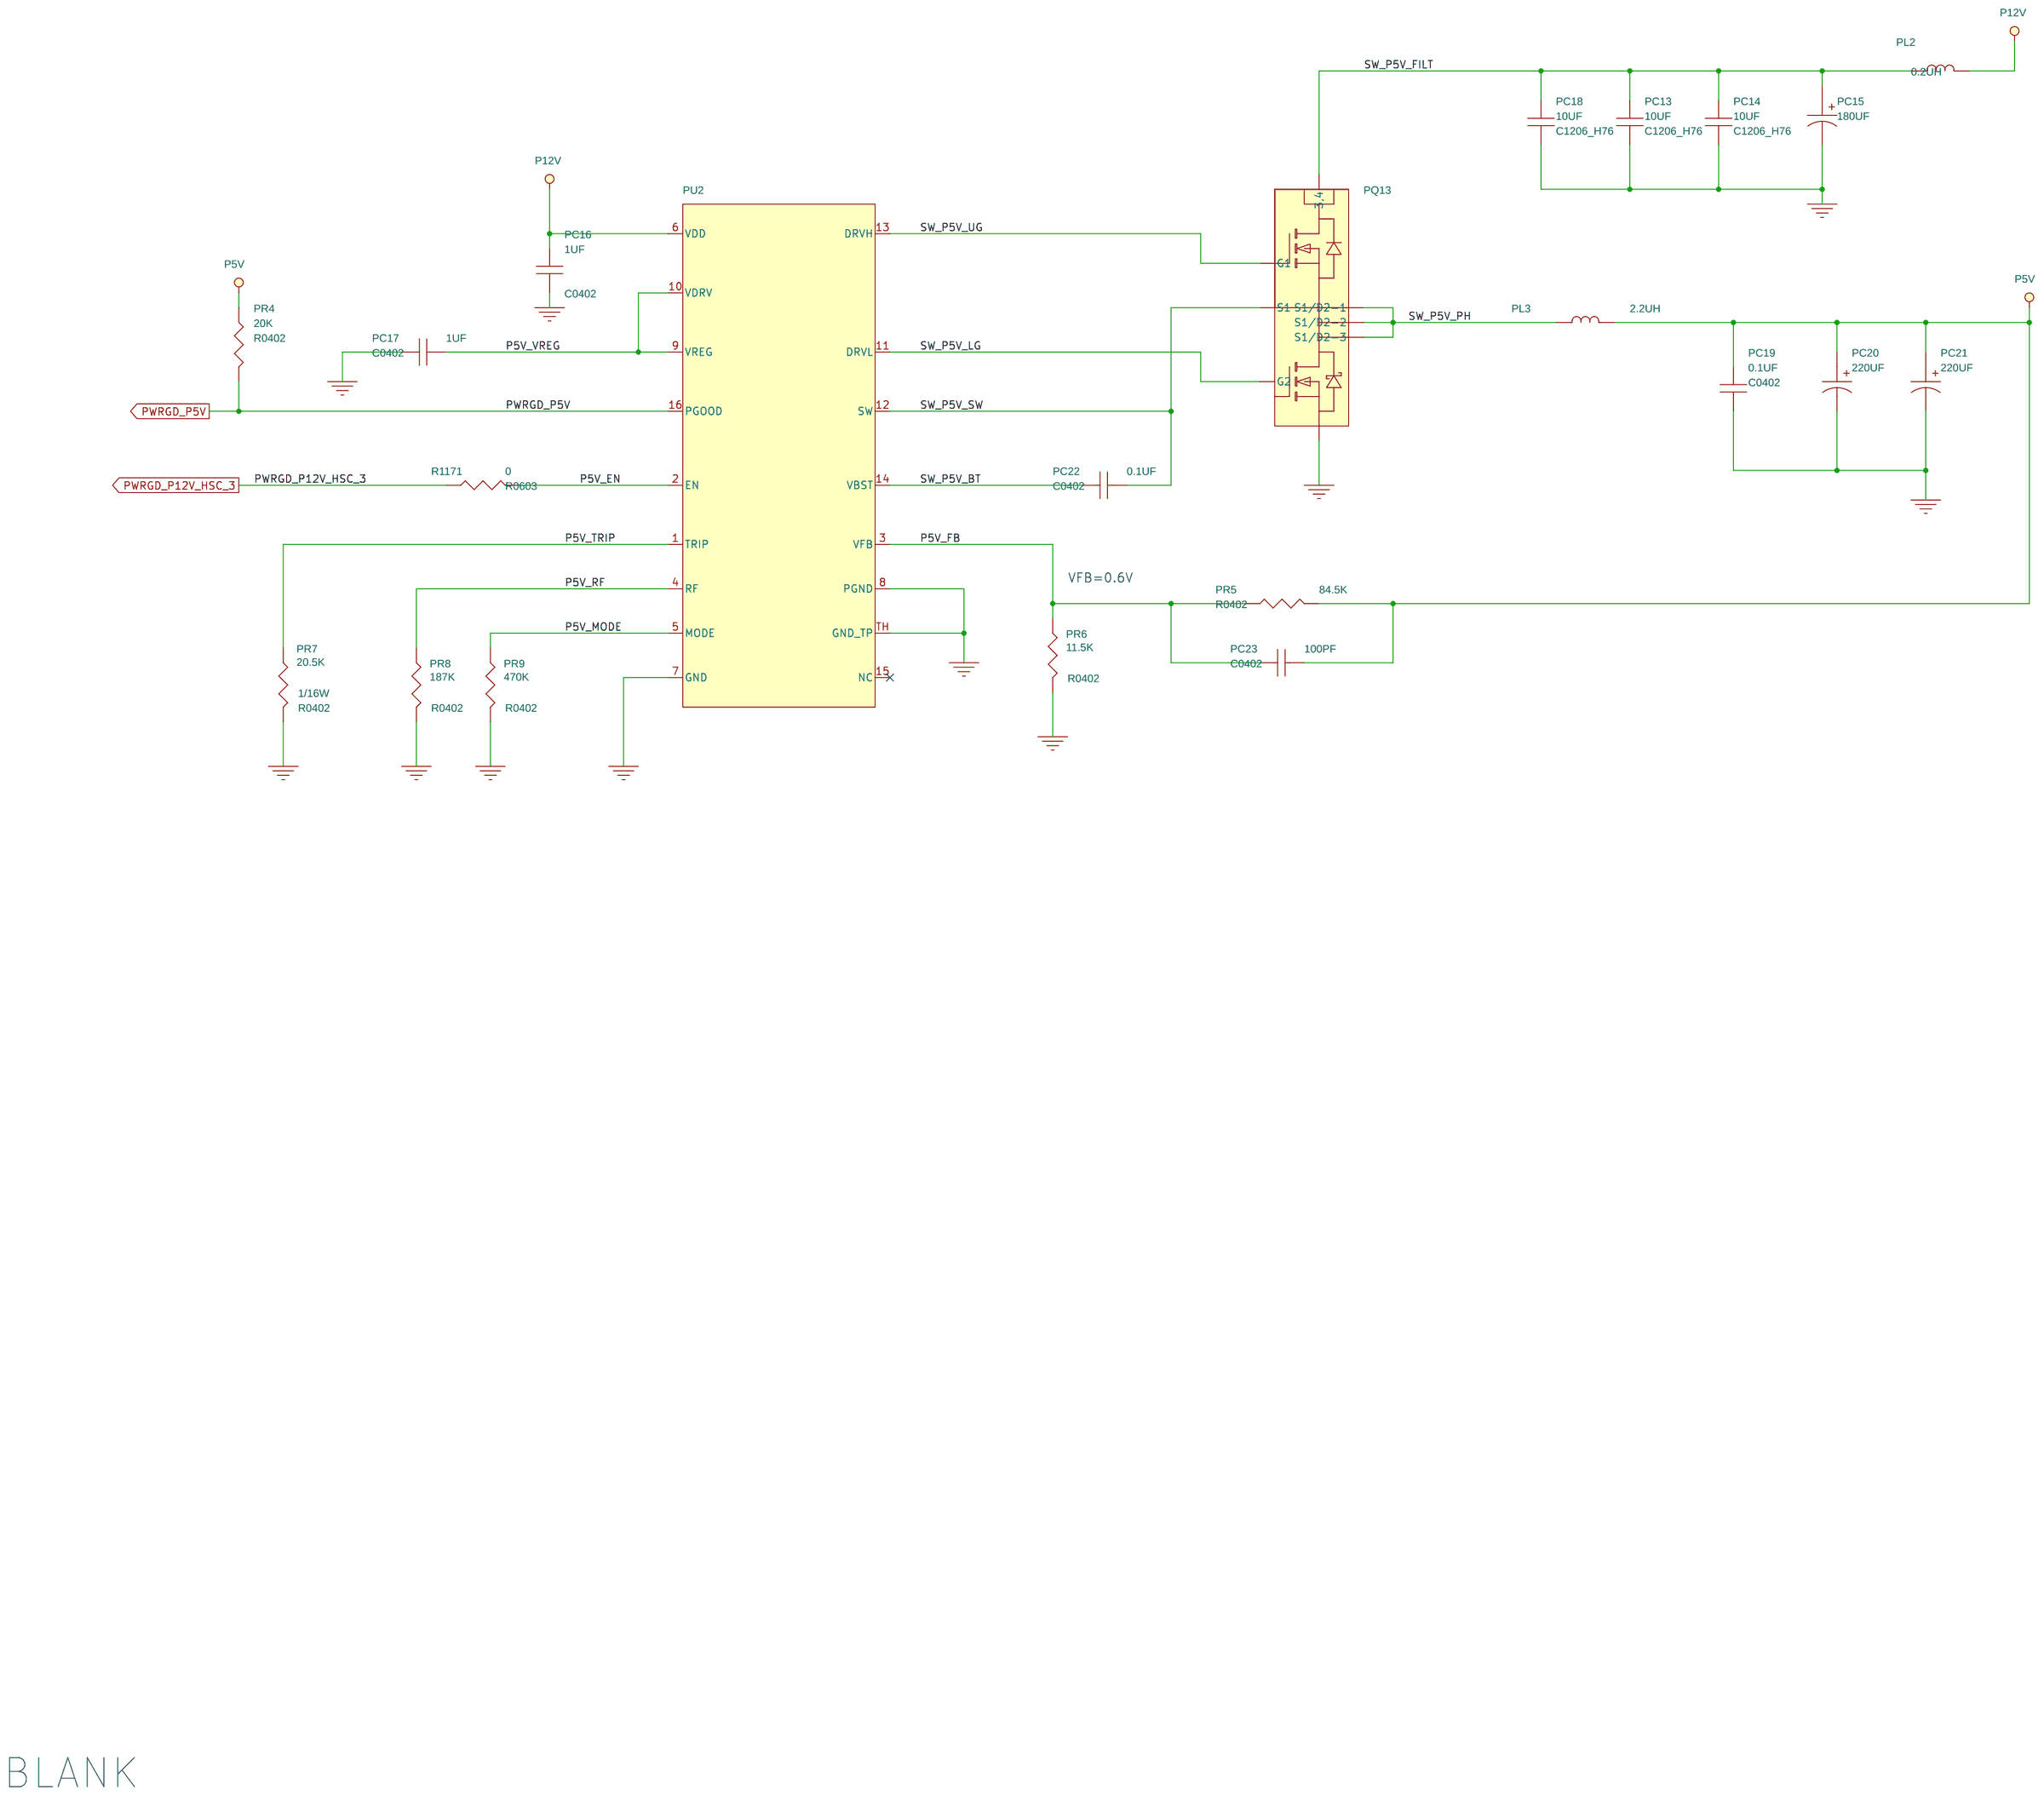
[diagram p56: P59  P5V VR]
58 P60  P3V3_STBY VR: size B
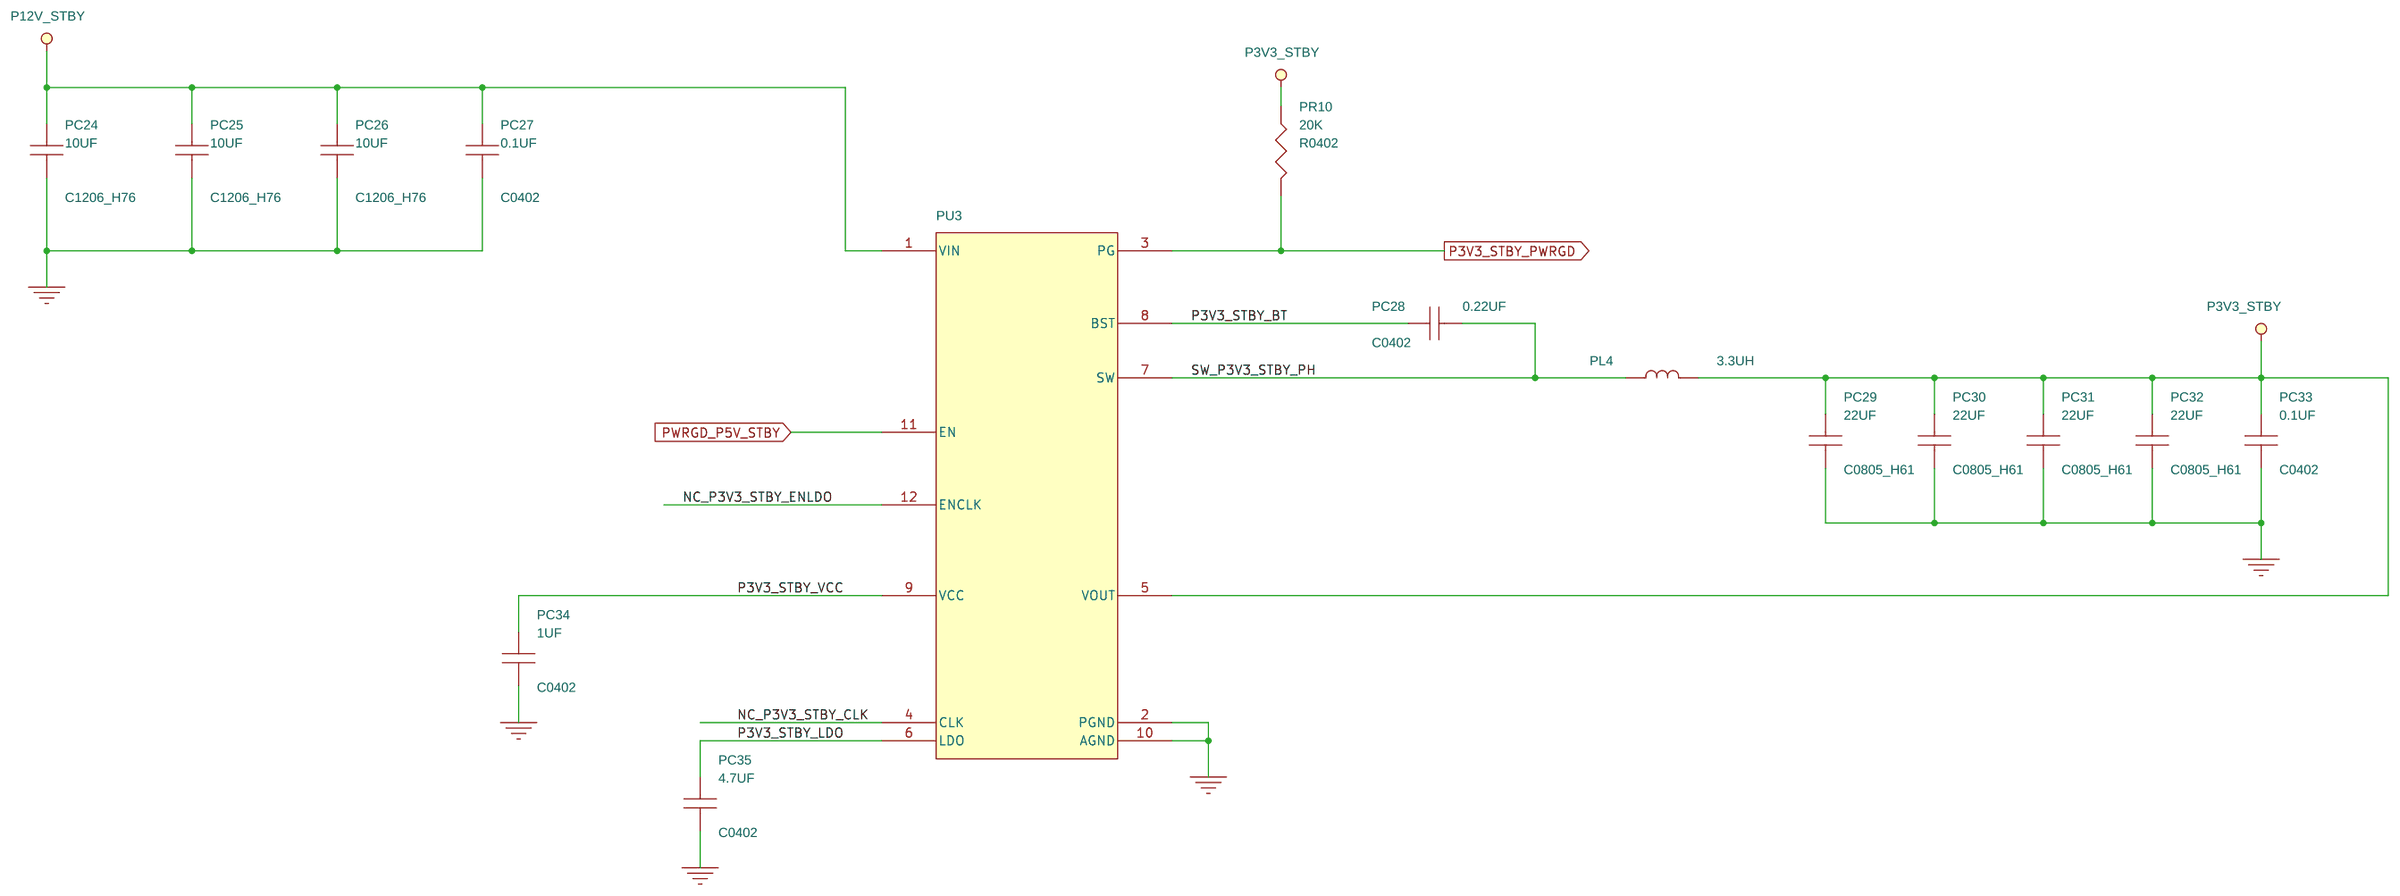
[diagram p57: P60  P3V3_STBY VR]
59 P61  P3V3 VR: size A2
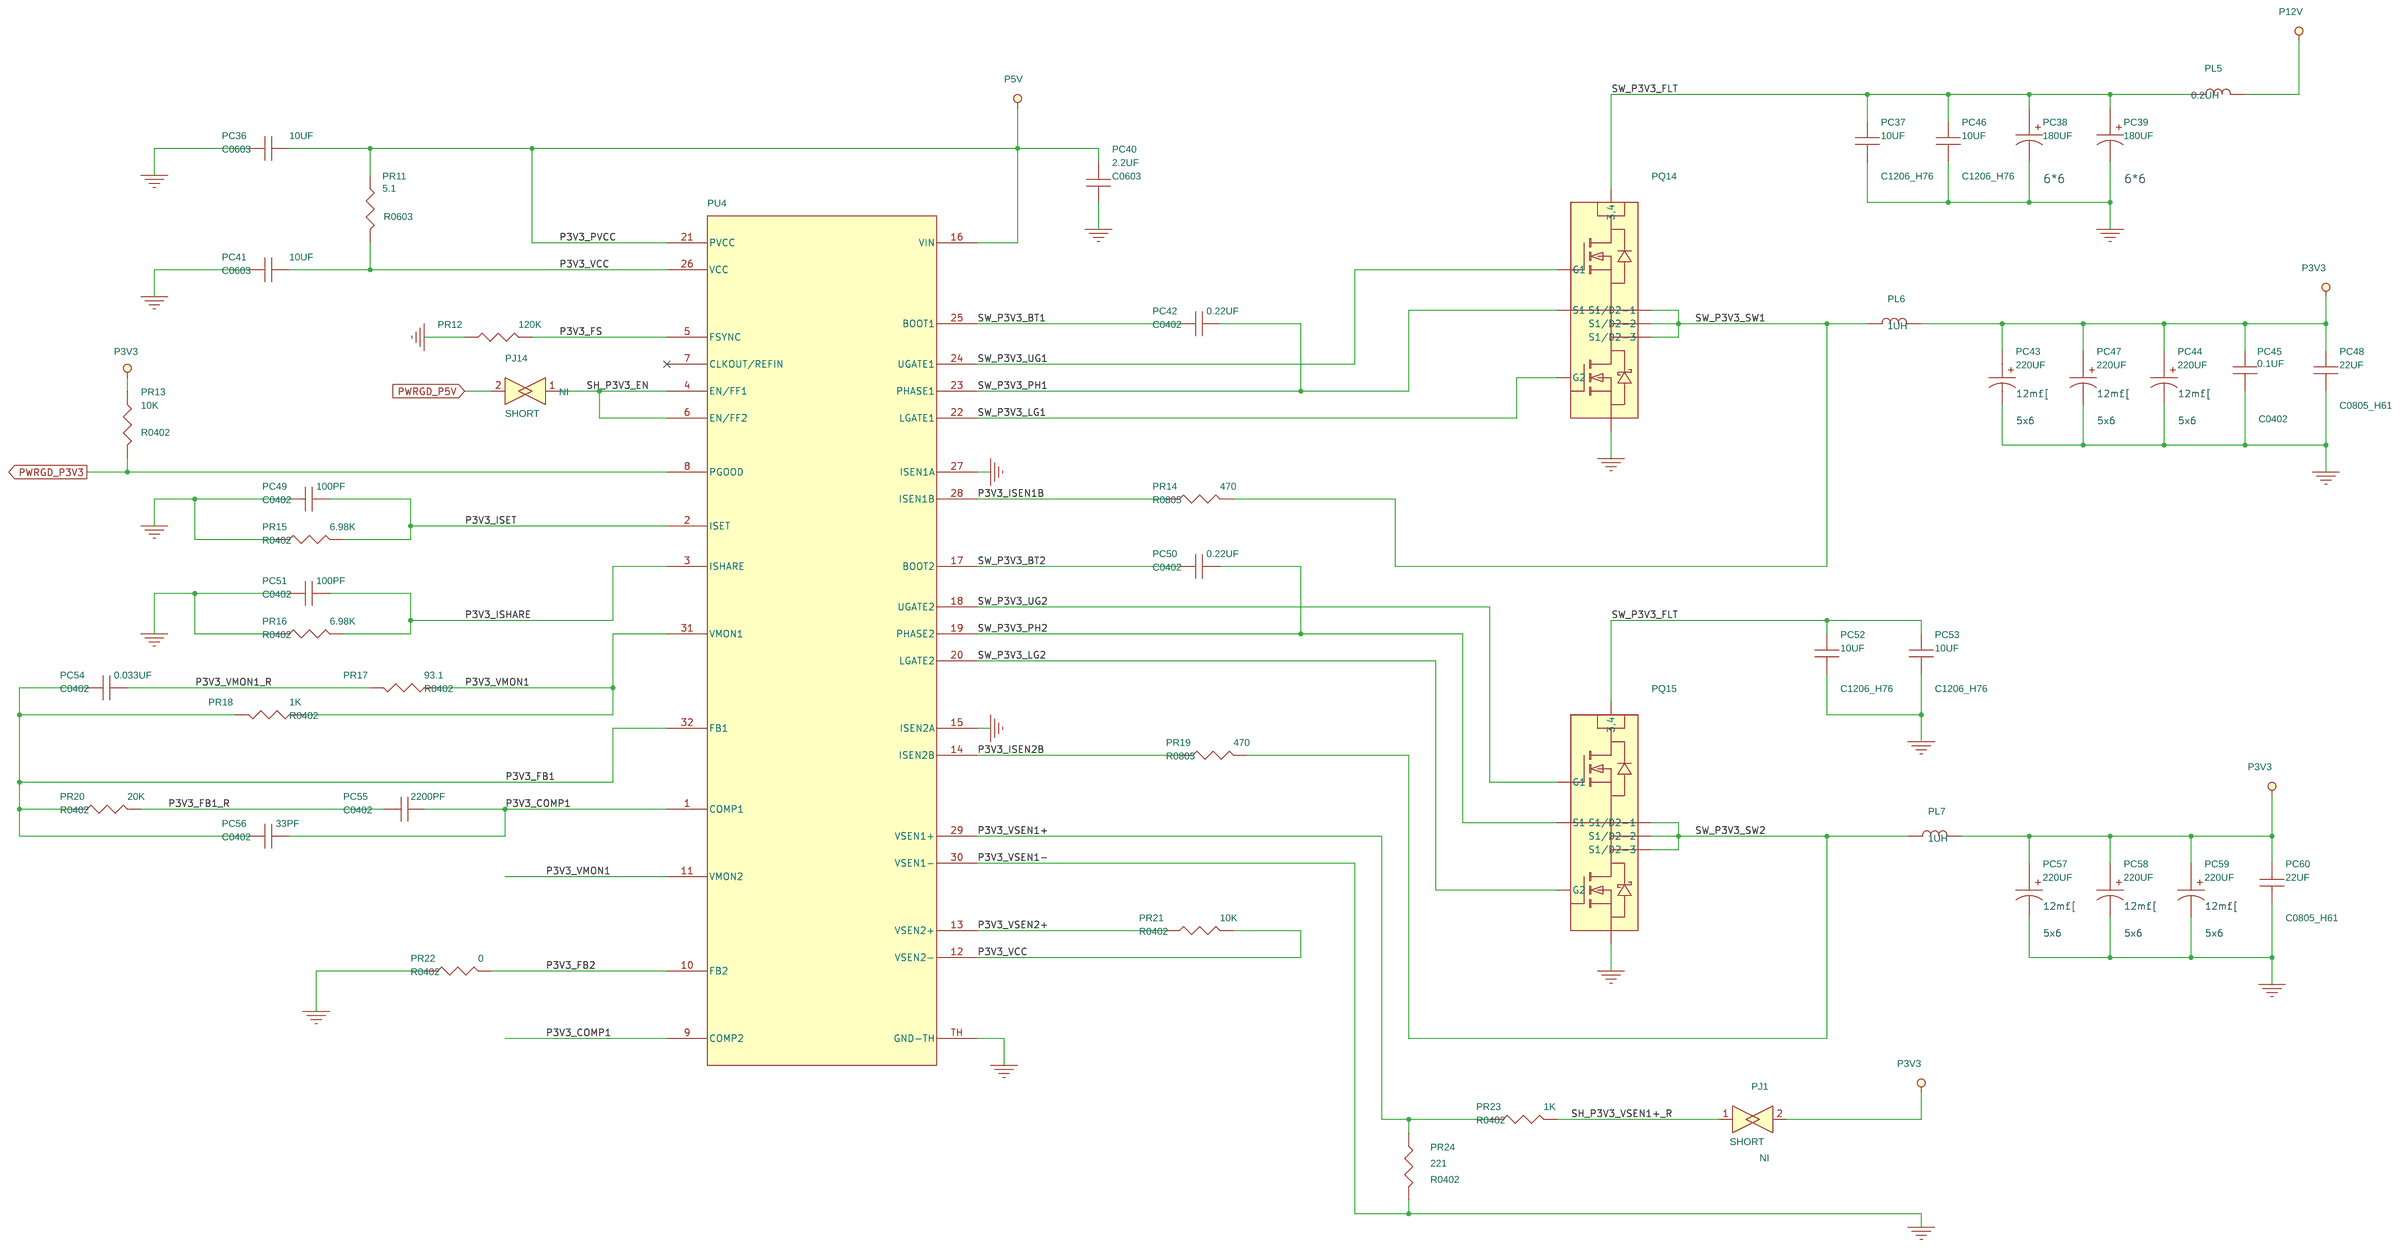
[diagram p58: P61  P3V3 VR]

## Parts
sheet P49  P12V_1 Hot Swap-2
C924  1UF  [C0402]
C925  1UF  [C0402]
C926  1UF  [C0402]
C927  1UF  [C0402]
C928  1000PF  [C0402]
C929  0.1UF  [C0402]
C930  0.01UF  [C0402]
C931  0.033UF  [C0603]
C932  0.1UF  [C0402]
C937  10UF  [C0805_H61]
C938  10UF  [C0805_H61]
C939  0.1UF  [C0402]
C940  0.1UF  [C0402]
CE29  270UF  [EC83_248_390S]
CE30  270UF  [EC83_248_390S]
D13  5.0SMDJ13A  [D2723_SMCXC]
D14  SBR15U30SP5-13  [POWERDI5XA]
J30  HEADER 1X2  [HEADER1X2XD]
PQ1  MOSFET  [SOT1023]
PQ2  MOSFET  [SOT1023]
PQ3  MOSFET  [SOT1023]
PQ4  MOSFET  [SOT1023]
Q27  METR3904-G  [SOT23_BEC]
Q28  MOSFET  [SOT23_GDSXC]
Q29  MOSFET  [SOT23_GDSXC]
R669  4.7K  [R0402]
R670  4.7K  [R0402]
R671  4.7K  [R0402]
R672  33  [R0402]
R673  33  [R0402]
R674  0  [R0402]
R675  0  [R0402]
R676  0  [R0402]
R677  82K  [R0402]
R678  82K  [R0402]
R679  100K  [R0402]
R680  31.6K  [R0402]
R681  0  [R0402]
R682  0  [R0402]
R683  31.6K  [R0402]
R684  100K  [R0402]
R685  10  [R0402]
R686  10  [R0402]
R687  10  [R0402]
R688  10  [R0402]
R689  10K  [R0402]
R690  0.0003  [R2725_4P]
R861  1M  [R0402]
R862  0.0003  [R2725_4P]
U13  IC  [LLP24_TH]
sheet P50  P12V_2 Hot Swap-0
C944  1UF  [C0402]
C945  1UF  [C0402]
C946  1UF  [C0402]
C947  1UF  [C0402]
C948  1000PF  [C0402]
C949  0.1UF  [C0402]
C950  0.01UF  [C0402]
C951  0.033UF  [C0603]
C952  0.1UF  [C0402]
C957  10UF  [C0805_H61]
C958  10UF  [C0805_H61]
C959  0.1UF  [C0402]
C960  0.1UF  [C0402]
CE31  270UF  [EC83_248_390S]
CE32  270UF  [EC83_248_390S]
D15  5.0SMDJ13A  [D2723_SMCXC]
D16  SBR15U30SP5-13  [POWERDI5XA]
J31  HEADER 1X2  [HEADER1X2XD]
PQ5  MOSFET  [SOT1023]
PQ6  MOSFET  [SOT1023]
PQ7  MOSFET  [SOT1023]
PQ8  MOSFET  [SOT1023]
Q30  METR3904-G  [SOT23_BEC]
Q31  MOSFET  [SOT23_GDSXC]
Q32  MOSFET  [SOT23_GDSXC]
R691  4.7K  [R0402]
R692  4.7K  [R0402]
R693  4.7K  [R0402]
R694  33  [R0402]
R695  33  [R0402]
R696  0  [R0402]
R697  0  [R0402]
R698  0  [R0402]
R699  82K  [R0402]
R700  82K  [R0402]
R701  100K  [R0402]
R702  0  [R0402]
R703  31.6K  [R0402]
R704  31.6K  [R0402]
R705  0  [R0402]
R706  100K  [R0402]
R707  10  [R0402]
R708  10  [R0402]
R709  10  [R0402]
R710  10  [R0402]
R711  10K  [R0402]
R712  0.0003  [R2725_4P]
R868  1M  [R0402]
R869  0.0003  [R2725_4P]
U14  IC  [LLP24_TH]
sheet P51  P12V Hot Swap-1
C964  1UF  [C0402]
C965  1UF  [C0402]
C966  1UF  [C0402]
C967  1UF  [C0402]
C968  1000PF  [C0402]
C969  0.1UF  [C0402]
C970  0.01UF  [C0402]
C971  0.033UF  [C0603]
C972  0.1UF  [C0402]
C977  10UF  [C0805_H61]
C978  10UF  [C0805_H61]
C979  0.1UF  [C0402]
C980  0.1UF  [C0402]
CE33  270UF  [EC83_248_390S]
CE34  270UF  [EC83_248_390S]
D17  5.0SMDJ13A  [D2723_SMCXC]
D18  SBR15U30SP5-13  [POWERDI5XA]
J32  HEADER 1X2  [HEADER1X2XD]
PQ9  MOSFET  [SOT1023]
PQ10  MOSFET  [SOT1023]
PQ11  MOSFET  [SOT1023]
PQ12  MOSFET  [SOT1023]
Q33  METR3904-G  [SOT23_BEC]
Q34  MOSFET  [SOT23_GDSXC]
Q35  MOSFET  [SOT23_GDSXC]
R713  4.7K  [R0402]
R714  4.7K  [R0402]
R715  4.7K  [R0402]
R716  33  [R0402]
R717  33  [R0402]
R718  0  [R0402]
R719  0  [R0402]
R720  0  [R0402]
R721  82K  [R0402]
R722  82K  [R0402]
R723  100K  [R0402]
R724  0  [R0402]
R725  31.6K  [R0402]
R726  31.6K  [R0402]
R727  0  [R0402]
R728  100K  [R0402]
R729  10  [R0402]
R730  10  [R0402]
R731  10  [R0402]
R732  10  [R0402]
R733  10K  [R0402]
R734  0.0003  [R2725_4P]
R875  1M  [R0402]
R876  0.0003  [R2725_4P]
U15  IC  [LLP24_TH]
sheet P52  Hardware Monitor
C984  0.1UF  [C0603]
C985  0.1UF  [C0603]
C986  0.1UF  [C0603]
C987  0.1UF  [C0603]
C988  0.1UF  [C0603]
C989  0.1UF  [C0603]
C990  0.1UF  [C0402]
C991  10UF  [C0805_H61]
C992  0.1UF  [C0402]
C993  10UF  [C0805_H61]
C994  0.1UF  [C0603]
C995  0.1UF  [C0603]
C996  0.1UF  [C0603]
C997  0.1UF  [C0603]
C998  0.1UF  [C0603]
C999  1UF  [C0402]
C1000  0.1UF  [C0402]
C1001  0.1UF  [C0402]
C1002  10UF  [C0805_H61]
C1389  0.1UF  [C0603]
L5  BLM11B601SP  [L0603]
L6  BLM11B601SP  [L0603]
L7  BLM15AG601SN1D  [L0402]
L8  BLM11B601SP  [L0603]
OSC1  33MHZ  [OSC4_FN]
R735  110K  [R0603]
R736  110K  [R0603]
R737  110K  [R0603]
R738  10K  [R0603]
R739  10K  [R0603]
R740  10K  [R0603]
R741  10K  [R0603]
R742  10K  [R0603]
R743  10K  [R0603]
R744  110K  [R0603]
R745  110K  [R0603]
R746  10K  [R0603]
R747  10K  [R0603]
R748  10K  [R0603]
R749  10K  [R0603]
R750  10K  [R0603]
R751  4.7K  [R0402]
R752  4.7K  [R0402]
R753  33  [R0402]
R754  4.7K  [R0402]
R755  33  [R0402]
R756  1M  [R0402]
R757  510  [R0603]
R759  4.7K  [R0402]
R760  4.7K  [R0402]
R761  100K  [R0402]
R762  100K  [R0402]
R763  8.2K  [R0402]
R764  100K  [R0402]
R765  100K  [R0402]
R766  33  [R0402]
R881  470  [R0402]
R882  470  [R0402]
R883  470  [R0402]
R1170  470  [R0402]
R1204  10K  [R0603]
R1205  110K  [R0603]
R1221  4.7K  [R0402]
U16  IC  [LQFP64]
sheet P53 Sytem Fan Module Connector
C1352  22UF  [C1206_H76]
C1353  22UF  [C1206_H76]
C1354  22UF  [C1206_H76]
C1355  22UF  [C1206_H76]
C1356  22UF  [C1206_H76]
C1357  22UF  [C1206_H76]
C1358  22UF  [C1206_H76]
C1359  22UF  [C1206_H76]
C1360  22UF  [C1206_H76]
C1361  22UF  [C1206_H76]
C1362  22UF  [C1206_H76]
C1363  22UF  [C1206_H76]
C1364  22UF  [C1206_H76]
C1365  22UF  [C1206_H76]
C1366  22UF  [C1206_H76]
C1367  22UF  [C1206_H76]
C1368  22UF  [C1206_H76]
C1369  22UF  [C1206_H76]
C1370  22UF  [C1206_H76]
C1371  22UF  [C1206_H76]
J22  SCONN36  [PCI-E_X1S_STRADDLEXA]
J23  SCONN36  [PCI-E_X1S_STRADDLEXA]
J24  SCONN36  [PCI-E_X1S_STRADDLEXA]
J25  SCONN36  [PCI-E_X1S_STRADDLEXA]
sheet P54  Sytem Fan Module
Q36  NX7002AKS  [SOT363XB]
Q37  NX7002AKS  [SOT363XB]
R784  10K  [R0402]
R785  10K  [R0402]
R786  10K  [R0402]
R787  4.7K  [R0402]
R788  10K  [R0402]
R789  4.7K  [R0402]
R790  4.7K  [R0402]
R791  10K  [R0402]
R792  4.7K  [R0402]
R793  10K  [R0402]
R794  4.7K  [R0402]
R795  10K  [R0402]
R796  4.7K  [R0402]
R797  10K  [R0402]
R798  4.7K  [R0402]
R799  4.7K  [R0402]
R800  10K  [R0402]
R801  10K  [R0402]
R802  10K  [R0402]
R803  10K  [R0402]
sheet P56  Reset Control Circuit-1
C1008  0.1UF  [C0402]
C1009  0.1UF  [C0402]
C1349  0.1UF  [C0402]
C1351  0.1UF  [C0402]
R825  4.7K  [R0402]
R826  4.7K  [R0402]
R1153  4.7K  [R0402]
R1177  4.7K  [R0402]
U22  MC74LVX50DTR2G  [TSSOP14]  (sections A,B,C,D,E,F)
U23  MC74LVX50DTR2G  [TSSOP14]  (sections A,B,C,D,E,F)
U103  MC74LVX50DTR2G  [TSSOP14]  (sections A,B,C,D,E,F)
U106  SN74LVC2G32DCUR  [SOP8]
sheet P57  Reset Control Circuit-2
C1010  0.1UF  [C0402]
R827  4.7K  [R0402]
R828  4.7K  [R0402]
R829  4.7K  [R0402]
R1152  4.7K  [R0402]
R1178  66.5  [R0402]
R1206  66.5  [R0402]
R1207  66.5  [R0402]
R1208  66.5  [R0402]
R1209  66.5  [R0402]
U99  74LVC07  [TSSOP14]  (sections A,B,C,D,E,F)
sheet P58  P5V_STBY VR
PC1447  180UF  [EC83_248_232S]
PC1448  0.1UF  [C0402]
PC1449  220UF  [EC56_197_229S]
PC1450  1UF  [C0402]
PC1451  1UF  [C0402]
PC1452  10UF  [C1206_H76]
PC1453  10UF  [C1206_H76]
PC1454  220UF  [EC56_197_229S]
PC1455  0.1UF  [C0402]
PC1456  100PF  [C0402]
PC1457  10UF  [C1206_H76]
PL22  2.2UH  [L_MMD12FD]
PL23  0.2UH  [L_MSI-600608]
PQ20  BSG0812ND  [PG-TISON8-4]
PR256  470K  [R0402]
PR257  84.5K  [R0402]
PR258  187K  [R0402]
PR259  11.5K  [R0402]
PR260  330K  [R0402]
PR261  20.5K  [R0402]
PU1  TPS53219RGT  [QFN16_THXG]
R1203  0  [R0603]
sheet P59  P5V VR
PC13  10UF  [C1206_H76]
PC14  10UF  [C1206_H76]
PC15  180UF  [EC83_248_232S]
PC16  1UF  [C0402]
PC17  1UF  [C0402]
PC18  10UF  [C1206_H76]
PC19  0.1UF  [C0402]
PC20  220UF  [EC56_197_229S]
PC21  220UF  [EC56_197_229S]
PC22  0.1UF  [C0402]
PC23  100PF  [C0402]
PL2  0.2UH  [L_MSI-600608]
PL3  2.2UH  [L_MMD12FD]
PQ13  BSG0812ND  [PG-TISON8-4]
PR4  20K  [R0402]
PR5  84.5K  [R0402]
PR6  11.5K  [R0402]
PR7  20.5K  [R0402]
PR8  187K  [R0402]
PR9  470K  [R0402]
PU2  IC  [QFN16_THXG]
R1171  0  [R0603]
sheet P60  P3V3_STBY VR
PC24  10UF  [C1206_H76]
PC25  10UF  [C1206_H76]
PC26  10UF  [C1206_H76]
PC27  0.1UF  [C0402]
PC28  0.22UF  [C0402]
PC29  22UF  [C0805_H61]
PC30  22UF  [C0805_H61]
PC31  22UF  [C0805_H61]
PC32  22UF  [C0805_H61]
PC33  0.1UF  [C0402]
PC34  1UF  [C0402]
PC35  4.7UF  [C0402]
PL4  3.3UH  [L_PCMB104TXB]
PR10  20K  [R0402]
PU3  IC  [QFN12_2X3]
sheet P61  P3V3 VR
PC36  10UF  [C0603]
PC37  10UF  [C1206_H76]
PC38  180UF  [EC83_248_232S]
PC39  180UF  [EC83_248_232S]
PC40  2.2UF  [C0603]
PC41  10UF  [C0603]
PC42  0.22UF  [C0402]
PC43  220UF  [EC56_197_229S]
PC44  220UF  [EC56_197_229S]
PC45  0.1UF  [C0402]
PC46  10UF  [C1206_H76]
PC47  220UF  [EC56_197_229S]
PC48  22UF  [C0805_H61]
PC49  100PF  [C0402]
PC50  0.22UF  [C0402]
PC51  100PF  [C0402]
PC52  10UF  [C1206_H76]
PC53  10UF  [C1206_H76]
PC54  0.033UF  [C0402]
PC55  2200PF  [C0402]
PC56  33PF  [C0402]
PC57  220UF  [EC56_197_229S]
PC58  220UF  [EC56_197_229S]
PC59  220UF  [EC56_197_229S]
PC60  22UF  [C0805_H61]
PJ1  SHORT  [SHORT_R0603]
PJ14  SHORT  [SHORT_R0402_M]
PL5  0.2UH  [L_MSI-600608]
PL6  1UH  [L_MMD12FD]
PL7  1UH  [L_MMD12FD]
PQ14  BSG0812ND  [PG-TISON8-4]
PQ15  BSG0812ND  [PG-TISON8-4]
PR11  5.1  [R0603]
PR12  120K  [R0402]
PR13  10K  [R0402]
PR14  470  [R0805]
PR15  6.98K  [R0402]
PR16  6.98K  [R0402]
PR17  93.1  [R0402]
PR18  1K  [R0402]
PR19  470  [R0805]
PR20  20K  [R0402]
PR21  10K  [R0402]
PR22  0  [R0402]
PR23  1K  [R0402]
PR24  221  [R0402]
PU4  IC  [QFN32_THXK]

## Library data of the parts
C924-C928 C930 C939 C940 C944-C948 C950 C959 C960 C964-C968 C970 C979 C980 C990 C992 C999-C1001 C1008-C1010 C1349 C1351 PC16 PC17 PC19 PC22 PC23 PC27 PC28 PC33-PC35 PC42 PC45 PC49-PC51 PC54-PC56 PC1448 PC1450 PC1451 PC1455 PC1456 = CAP_NP: Part_Type: *LF_C0402
C929 C932 C949 C952 C969 C972 = CAP_NP: Not_insert: NI; Part_Type: *LF_C0402
C931 C951 C971 C984-C989 C994-C998 C1389 PC36 PC40 PC41 = CAP_NP: Part_Type: *LF_C0603
C937 C938 C957 C958 C977 C978 C991 C993 C1002 PC29-PC32 PC48 PC60 = CAP_NP: Part_Type: *LF_C0805
CE29-CE34 PC15 PC20 PC21 PC38 PC39 PC43 PC44 PC47 PC57-PC59 PC1447 PC1449 PC1454 = CAPACITOR_POL: Part_Type: *LF_C_ELEC_SMD
D13 D15 D17 = SMBJ13CA: Part_Type: *LF_Semiconductor
D14 D16 D18 = SPL1040PT: Not_insert: NI; Part_Type: *LF_Semiconductor
J30-J32 = DIP_2PIN: Part_Type: *LF_Connector
PQ1-PQ12 = MOSFET_NCH_1D3S: Part_Type: *LF_Semiconductor
Q27 Q30 Q33 = NPN_0: Part_Type: *LF_Semiconductor
Q28 Q29 Q31 Q32 Q34 Q35 = MOSFET_N_GSD: Part_Type: *LF_Semiconductor
R669-R671 R691-R693 R713-R715 R764 R765 = R_0: Not_insert: NI; Part_Type: *LF_Resistor; WATTAGE: 1/16W
PR4-PR10 PR12 PR13 PR15-PR18 PR20-PR24 PR256-PR261 R672-R680 R683-R689 R694-R696 R699-R704 R706-R711 R716-R718 R720-R726 R728-R733 R784-R786 R788 R791 R793 R795 R797 R800-R803 R828 R829 R881-R883 R1152 R1170 R1178 R1206-R1209 = R: Part_Type: *LF_Resistor; WATTAGE: 1/16W
R681 R682 R697 R698 R719 R727 R825-R827 R861 R868 R875 R1153 R1177 = R: Not_insert: NI; Part_Type: *LF_Resistor; WATTAGE: 1/16W
R690 R712 R734 R862 R869 R876 = Q_SP_RES4P: Part_Type: *LF_Resistor; WATTAGE: 4W
U13-U15 = SN1402039SQXNOPB: Part_Type: *LF_Chipset
R705 = R: Not_insert: <Not_insert>; Part_Type: *LF_Resistor; WATTAGE: 1/16W
L5-L8 PL2-PL7 PL22 PL23 = L: Part_Type: *LF_Inductor
OSC1 = OSC-4: Part_Type: *LF_Misc
PR11 R735-R737 R744 R745 R1171 R1203 R1205 = R: Part_Type: *LF_Resistor; WATTAGE: 1/10W
R738-R743 R746-R750 R1204 = R: Part_Type: Resistor; WATTAGE: 1/10W
R751-R756 R759-R763 R766 R787 R789 R790 R792 R794 R796 R798 R799 R1221 = R_0: Part_Type: *LF_Resistor; WATTAGE: 1/16W
R757 = R_0: Part_Type: *LF_Resistor; WATTAGE: 1/10W
U16 = W83795G: Part_Type: *LF_Chipset
C1352-C1371 PC13 PC14 PC18 PC24-PC26 PC37 PC46 PC52 PC53 PC1452 PC1453 PC1457 = CAP_NP: Part_Type: *LF_C1206
J22-J25 = PCI_EXPRESS_1X_CONN_3: Part_Type: *LF_Connector
Q36 Q37 = MOSFET_DUAL_6P: Part_Type: *LF_Semiconductor
U22 U23 U103 = 74LVC07: Part_Type: *LF_Chipset
U106 = SN74LVC2G32DCUR: Part_Type: *LF_Chipset
U99 = 74LVC07: Part_Type: Chipset; Preference: TOSHIBA
PQ13-PQ15 PQ20 = MOSFET_NCH_DUAL_1D1S: Part_Type: *LF_Semiconductor
PU1 PU2 = TPS53219RGT: Part_Type: *LF_Chipset
PU3 = NB680GDZ: Part_Type: *LF_Chipset
PJ1 PJ14 = JUMPER-2_1: Not_insert: NI; Part_Type: Mech
PR14 PR19 = R: Part_Type: *LF_Resistor; WATTAGE: 1/8W
PU4 = ISL8120CRZT: Part_Type: *LF_Chipset

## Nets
3.3V_1: J22.A9(3.3V_1) J23.A9(3.3V_1) J24.A9(3.3V_1) J25.A9(3.3V_1)
3.3V_2: J22.A10(3.3V_2) J23.A10(3.3V_2) J24.A10(3.3V_2) J25.A10(3.3V_2)
3.3VAUX: J22.B10(3.3VAUX) J23.B10(3.3VAUX) J24.B10(3.3VAUX) J25.B10(3.3VAUX)
AGND_HWMON: L8.1 U16.2(AGND)
GND: C925.2 C926.2 C927.2 C928.2 C929.2 C930.2 C931.2 C932.2 C937.2 C938.2 C939.2 C940.2 C945.2 C946.2 C947.2 C948.2 C949.2 C950.2 C951.2 C952.2 C957.2 C958.2 C959.2 C960.2 C965.2 C966.2 C967.2 C968.2 C969.2 C970.2 C971.2 C972.2 C977.2 C978.2 C979.2 C980.2 C984.2 C985.2 C986.2 C987.2 C988.2 C989.2 C990.2 C991.2 C992.2 C993.2 C994.2 C995.2 C996.2 C997.2 C998.2 C999.2 C1000.2 C1001.2 C1002.2 C1008.2 C1009.2 C1010.2 C1349.2 C1351.2 C1352.2 C1353.2 C1354.2 C1355.2 C1356.2 C1357.2 C1358.2 C1359.2 C1360.2 C1361.2 C1362.2 C1363.2 C1364.2 C1365.2 C1366.2 C1367.2 C1368.2 C1369.2 C1370.2 C1371.2 C1389.2 CE29.2 CE30.2 CE31.2 CE32.2 CE33.2 CE34.2 D13.A D14.1(ANODE) D14.2(Anode) D15.A D16.1(ANODE) D16.2(Anode) D17.A D18.1(ANODE) D18.2(Anode) J22.B4(GND_0) J22.B7(GND_1) J22.B13(GND_2) J22.B16(GND_3) J22.B18(GND_4) J23.B4(GND_0) J23.B7(GND_1) J23.B13(GND_2) J23.B16(GND_3) J23.B18(GND_4) J24.B4(GND_0) J24.B7(GND_1) J24.B13(GND_2) J24.B16(GND_3) J24.B18(GND_4) J25.B4(GND_0) J25.B7(GND_1) J25.B13(GND_2) J25.B16(GND_3) J25.B18(GND_4) J30.1 J31.1 J32.1 L8.2 OSC1.2(GND) PC13.2 PC14.2 PC15.2 PC16.2 PC17.1 PC18.2 PC19.2 PC20.2 PC21.2 PC24.2 PC25.2 PC26.2 PC27.2 PC29.2 PC30.2 PC31.2 PC32.2 PC33.2 PC34.2 PC35.2 PC36.1 PC37.2 PC38.2 PC39.2 PC40.1 PC41.1 PC43.2 PC44.2 PC45.2 PC46.2 PC47.2 PC48.2 PC49.1 PC51.1 PC52.2 PC53.2 PC57.2 PC58.2 PC59.2 PC60.2 PC1447.2 PC1449.2 PC1450.1 PC1451.2 PC1452.2 PC1453.2 PC1454.2 PC1455.2 PC1457.2 PQ13.S2 PQ14.S2 PQ15.S2 PQ20.S2 PR6.2 PR7.2 PR8.2 PR9.2 PR12.1 PR15.1 PR16.1 PR22.1 PR24.2 PR256.2 PR258.2 PR259.2 PR261.2 PU1.7(GND) PU1.8(PGND) PU1.TH(GND_TP) PU2.7(GND) PU2.8(PGND) PU2.TH(GND_TP) PU3.2(PGND) PU3.10(AGND) PU4.15(ISEN2A) PU4.27(ISEN1A) PU4.30(VSEN1-) PU4.TH(GND-TH) Q27.E(2) Q28.S(SOURCE) Q29.S(SOURCE) Q30.E(2) Q31.S(SOURCE) Q32.S(SOURCE) Q33.E(2) Q34.S(SOURCE) Q35.S(SOURCE) Q36.1(S1) Q36.4(S2) Q37.1(S1) Q37.4(S2) R680.1 R681.2 R682.2 R683.1 R684.1 R702.2 R703.1 R704.1 R705.2 R706.1 R724.2 R725.1 R726.1 R727.2 R728.1 R741.2 R742.2 R743.2 R749.2 R750.2 R764.2 R765.2 R787.2 R789.2 R790.2 R792.2 R794.2 R796.2 R798.2 R799.2 R861.2 R868.2 R875.2 R1204.2 U13.2(GND1) U13.11(GPIO0) U13.12(GPIO1) U13.16(DGND) U13.TH U14.2(GND1) U14.11(GPIO0) U14.12(GPIO1) U14.16(DGND) U14.TH U15.2(GND1) U15.11(GPIO0) U15.12(GPIO1) U15.16(DGND) U15.TH U16.56(GND) U22.7(GND) U23.1(IN) U23.3(IN) U23.7(GND) U99.7(GND) U103.7(GND) U106.4(GND) U106.5(2A) U106.6(2B) ; also on sheet 3 4 5 6 7 8 9 10 11 12 13 14 15 16 17 18 19 20 21 22 23 24 25 26 27 28 29 30 31 32 33 34 35 36 37 38 39 40 41 42 43 44 45 46 47 60 61 62 63 64 65 66 67
GND_5: J22.A4(GND_5) J23.A4(GND_5) J24.A4(GND_5) J25.A4(GND_5)
GND_6: J22.A12(GND_6) J23.A12(GND_6) J24.A12(GND_6) J25.A12(GND_6)
GND_7: J22.A15(GND_7) J23.A15(GND_7) J24.A15(GND_7) J25.A15(GND_7)
GND_8: J22.A18(GND_8) J23.A18(GND_8) J24.A18(GND_8) J25.A18(GND_8)
P0V9A_PLX1: R740.1 ; also on sheet 12 14 64
P0V9A_PLX1_SCALED: C989.1 R740.2 U16.14((VDD1/VCORE2)VSEN2)
P0V9A_PLX2: R748.1 ; also on sheet 24 26 65
P0V9A_PLX2_SCALED: C998.1 R748.2 U16.13((VDD0/VCORE1)VSEN1)
P0V9D_PLX1: R739.1 ; also on sheet 12 14 62
P0V9D_PLX1_SCALED: C988.1 R739.2 U16.16(VSEN4)
P0V9D_PLX2: R747.1 ; also on sheet 24 26 63
P0V9D_PLX2_SCALED: C997.1 R747.2 U16.15((VDDNB/VCORE3)VSEN3)
P1V8_HSC_1: C925.1 U13.17(V1P8)
P1V8_HSC_2: C945.1 U14.17(V1P8)
P1V8_HSC_3: C965.1 U15.17(V1P8)
P1V8D_PLX1: R738.1 ; also on sheet 9 10 11 12 14 46 60
P1V8D_PLX2: R746.1 ; also on sheet 21 22 23 24 26 46 61
P1V8D_PLX_1_SCALED: C987.1 R738.2 U16.18(VSEN6)
P1V8D_PLX_2_SCALED: C996.1 R746.2 U16.17(VSEN5)
P3V3: C999.1 L6.2 L7.2 PC43.1 PC44.1 PC45.1 PC47.1 PC48.1 PC57.1 PC58.1 PC59.1 PC60.1 PJ1.2 PL6.2 PL7.2 PR13.1 R745.1 R751.2 R752.2 R754.2 R756.2 R757.2 R763.1 R784.2 R785.2 R786.2 R788.2 R791.2 R793.2 R795.2 R797.2 R800.2 R801.2 R802.2 R803.2 R1205.1 ; also on sheet 10 22 27 28 31 32 33 34 35 36 37 38 41 44 60 61 62 63 64 65 66
P3V3_COMP1: PC55.1 PC56.2 PU4.1(COMP1) PU4.9(COMP2)
P3V3_FB1: PC54.1 PC56.1 PR18.2 PR20.1 PU4.32(FB1)
P3V3_FB1_R: PC55.2 PR20.2
P3V3_FB2: PR22.2 PU4.10(FB2)
P3V3_FS: PR12.2 PU4.5(FSYNC)
P3V3_HSC_1: C927.1 R675.2 R676.2 U13.20(VDD)
P3V3_HSC_2: C947.1 R697.2 R698.2 U14.20(VDD)
P3V3_HSC_3: C967.1 R719.2 R720.2 U15.20(VDD)
P3V3_HWM_VDD: C992.1 C993.1 L6.1 U16.24(3VDD)
P3V3_HWM_VSB: C990.1 C991.1 L5.1 U16.25(3VSB)
P3V3_ISEN1B: PR14.1 PU4.28(ISEN1B)
P3V3_ISEN2B: PR19.1 PU4.14(ISEN2B)
P3V3_ISET: PC49.2 PR15.2 PU4.2(ISET)
P3V3_ISHARE: PC51.2 PR16.2 PU4.3(ISHARE)
P3V3_SCALED: C995.1 R745.2 R750.1 U16.19(VSEN7)
P3V3_STBY: C1008.1 C1009.1 C1010.1 C1349.1 C1351.1 L5.2 PC29.1 PC30.1 PC31.1 PC32.1 PC33.1 PL4.2 PR10.1 PU3.5(VOUT) R669.2 R670.2 R671.2 R691.2 R692.2 R693.2 R713.2 R714.2 R715.2 R737.1 R759.2 R760.2 R761.1 R762.1 R825.1 R826.1 R827.1 R828.1 R829.1 R1152.1 R1153.1 R1177.1 R1221.2 U22.14(VCC) U23.14(VCC) U99.14(VCC) U103.14(VCC) U106.8(VCC) ; also on sheet 27 28 29 30 31 32 33 34 35 36 37 38 39 40 43 44 45 46 67
P3V3_STBY_BT: PC28.1 PU3.8(BST)
P3V3_STBY_LDO: PC35.1 PU3.6(LDO)
P3V3_STBY_PWRGD: PR10.2 PU3.3(PG)
P3V3_STBY_SCALED: C986.1 R737.2 R743.1 U16.20(VSEN8)
P3V3_STBY_VCC: PC34.1 PU3.9(VCC)
P3V3_VCC: PC41.2 PR11.2 PR21.2 PU4.12(VSEN2-) PU4.26(VCC)
P3V3_VMON1: PR17.1 PR18.1 PU4.11(VMON2) PU4.31(VMON1)
P3V3_VMON1_R: PC54.2 PR17.2
P3V3_VSEN1+: PR23.1 PR24.1 PU4.29(VSEN1+)
P3V3_VSEN2+: PR21.1 PU4.13(VSEN2+)
P5V: PC19.1 PC20.1 PC21.1 PC23.2 PC36.2 PC40.2 PL3.2 PR4.1 PR5.2 PR11.1 PU4.16(VIN) PU4.21(PVCC) R744.1 ; also on sheet 41 60 61 62 63 66
P5V_EN: PU2.2(EN) R1171.2
P5V_FB: PC23.1 PR5.1 PR6.1 PU2.3(VFB)
P5V_MODE: PR9.1 PU2.5(MODE)
P5V_RF: PR8.1 PU2.4(RF)
P5V_SCALED: C994.1 R744.2 R749.1 U16.21(VSEN9)
P5V_STBY: PC1449.1 PC1454.1 PC1455.1 PC1456.2 PL22.2 PR257.2 PR260.1 R736.1 ; also on sheet 41 44 45
P5V_STBY_EN: PU1.2(EN) R1203.2
P5V_STBY_FB: PC1456.1 PR257.1 PR259.1 PU1.3(VFB)
P5V_STBY_MODE: PR256.1 PU1.5(MODE)
P5V_STBY_RF: PR258.1 PU1.4(RF)
P5V_STBY_SCALED: C985.1 R736.2 R742.1 U16.22(VSEN10)
P5V_STBY_TRIP: PR261.1 PU1.1(TRIP)
P5V_STBY_VREG: PC1450.2 PU1.9(VREG) PU1.10(VDRV)
P5V_TRIP: PR7.1 PU2.1(TRIP)
P5V_VREG: PC17.2 PU2.9(VREG) PU2.10(VDRV)
P12V: C977.1 C978.1 C979.1 C980.1 CE33.1 CE34.1 D18.3(Cathod) PC16.1 PL2.2 PL5.2 PQ9.1 PQ9.2 PQ9.3 PQ10.1 PQ10.2 PQ10.3 PQ11.1 PQ11.2 PQ11.3 PQ12.1 PQ12.2 PQ12.3 PU2.6(VDD) R722.2 U15.24(VOUT) ; also on sheet 34 35 41 42 66
P12V_1: C937.1 C938.1 C939.1 C940.1 C1352.1 C1353.1 C1354.1 C1355.1 C1356.1 C1367.1 C1368.1 C1369.1 C1370.1 C1371.1 CE29.1 CE30.1 D14.3(Cathod) J22.A2(12V_3) J22.A3(12V_4) J22.B1(12V_0) J22.B2(12V_1) J22.B3(12V_2) J24.A2(12V_3) J24.A3(12V_4) J24.B1(12V_0) J24.B2(12V_1) J24.B3(12V_2) PQ1.1 PQ1.2 PQ1.3 PQ2.1 PQ2.2 PQ2.3 PQ3.1 PQ3.2 PQ3.3 PQ4.1 PQ4.2 PQ4.3 R678.2 U13.24(VOUT) ; also on sheet 31 32 33 42 60 62 64
P12V_2: C957.1 C958.1 C959.1 C960.1 C1357.1 C1358.1 C1359.1 C1360.1 C1361.1 C1362.1 C1363.1 C1364.1 C1365.1 C1366.1 CE31.1 CE32.1 D16.3(Cathod) J23.A2(12V_3) J23.A3(12V_4) J23.B1(12V_0) J23.B2(12V_1) J23.B3(12V_2) J25.A2(12V_3) J25.A3(12V_4) J25.B1(12V_0) J25.B2(12V_1) J25.B3(12V_2) PQ5.1 PQ5.2 PQ5.3 PQ6.1 PQ6.2 PQ6.3 PQ7.1 PQ7.2 PQ7.3 PQ8.1 PQ8.2 PQ8.3 R700.2 U14.24(VOUT) ; also on sheet 36 37 38 42 61 63 65
P12V_HSC_1_ADR0: R676.1 R682.1 U13.18(ADR0)
P12V_HSC_1_ADR1: R675.1 R681.1 U13.19(ADR1)
P12V_HSC_1_BUF_EN: Q29.G(GATE) R684.2 ; also on sheet 67
P12V_HSC_1_EN: C930.1 Q28.D(DRAIN) R677.1 R683.2 U13.10(EN)
P12V_HSC_1_EN_N: J30.2 Q28.G(GATE) Q29.D(DRAIN) R679.1
P12V_HSC_1_FLT_N: C924.1 U13.8(FLT_N)
P12V_HSC_1_FLT_P: C924.2 U13.7(FLT_P)
P12V_HSC_1_GATE: R685.2 R686.2 R687.2 R688.2 R689.2 U13.1(GATE)
P12V_HSC_1_SENSE_N: R690.1B R862.1B U13.3(SNS_N)
P12V_HSC_1_SENSE_P: R690.2B R862.2B U13.5(SNS_P)
P12V_HSC_1_SW: PQ1.5 PQ2.5 PQ3.5 PQ4.5 R690.1A R862.1A
P12V_HSC_1_TEMP: C928.1 Q27.B(1) Q27.C(3) U13.22(DIODE)
P12V_HSC_2_ADR0: R698.1 R705.1 U14.18(ADR0)
P12V_HSC_2_ADR1: R697.1 R702.1 U14.19(ADR1)
P12V_HSC_2_BUF_EN: Q32.G(GATE) R706.2 ; also on sheet 67
P12V_HSC_2_EN: C950.1 Q31.D(DRAIN) R699.1 R703.2 U14.10(EN)
P12V_HSC_2_EN_N: J31.2 Q31.G(GATE) Q32.D(DRAIN) R701.1
P12V_HSC_2_FLT_N: C944.1 U14.8(FLT_N)
P12V_HSC_2_FLT_P: C944.2 U14.7(FLT_P)
P12V_HSC_2_GATE: R707.2 R708.2 R709.2 R710.2 R711.2 U14.1(GATE)
P12V_HSC_2_SENSE_N: R712.1B R869.1B U14.3(SNS_N)
P12V_HSC_2_SENSE_P: R712.2B R869.2B U14.5(SNS_P)
P12V_HSC_2_SW: PQ5.5 PQ6.5 PQ7.5 PQ8.5 R712.1A R869.1A
P12V_HSC_2_TEMP: C948.1 Q30.B(1) Q30.C(3) U14.22(DIODE)
P12V_HSC_3_ADR0: R720.1 R727.1 U15.18(ADR0)
P12V_HSC_3_ADR1: R719.1 R724.1 U15.19(ADR1)
P12V_HSC_3_BUF_EN: Q35.G(GATE) R728.2 ; also on sheet 67
P12V_HSC_3_EN: C970.1 Q34.D(DRAIN) R721.1 R725.2 U15.10(EN)
P12V_HSC_3_EN_N: J32.2 Q34.G(GATE) Q35.D(DRAIN) R723.1
P12V_HSC_3_FLT_N: C964.1 U15.8(FLT_N)
P12V_HSC_3_FLT_P: C964.2 U15.7(FLT_P)
P12V_HSC_3_GATE: R729.2 R730.2 R731.2 R732.2 R733.2 U15.1(GATE)
P12V_HSC_3_SENSE_N: R734.1B R876.1B U15.3(SNS_N)
P12V_HSC_3_SENSE_P: R734.2B R876.2B U15.5(SNS_P)
P12V_HSC_3_SW: PQ9.5 PQ10.5 PQ11.5 PQ12.5 R734.1A R876.1A
P12V_HSC_3_TEMP: C968.1 Q33.B(1) Q33.C(3) U15.22(DIODE)
P12V_PSU: C926.1 C932.1 C946.1 C952.1 C966.1 C972.1 D13.C D15.C D17.C R677.2 R679.2 R690.2A R699.2 R701.2 R712.2A R721.2 R723.2 R734.2A R862.2A R869.2A R876.2A U13.9(VIN) U14.9(VIN) U15.9(VIN) ; also on sheet 47
P12V_STBY: PC24.1 PC25.1 PC26.1 PC27.1 PC1451.1 PL23.2 PU1.6(VDD) PU3.1(VIN) R735.1 ; also on sheet 47
P12V_STBY_PWRGD: R1203.1 ; also on sheet 47
P12V_STBY_SCALED: C984.1 R735.2 R741.1 U16.23(VSEN11)
CLK_33M_HWMON: R766.2 U16.32(CLKIN)
CLK_33M_HWMON_OE: OSC1.1(OE) R763.2
CLK_33M_HWMON_OUT: OSC1.3(OUT) R766.1
CLK_33M_HWMON_VDD: C1001.1 C1002.1 L7.1 OSC1.4(VDD)
GPU_BOARD_ID: C1389.1 R1204.1 R1205.2 U16.4(VSEN13/TR6)
HWM_CASEOPEN_N: R756.1 U16.27(CASEOPEN#)
HWM_VBAT: R757.1 U16.26(VBAT)
HWMON_ADDR0: R762.2 R765.1 U16.41(FANCLT1/ADDR0)
HWMON_ADDR1: R761.2 R764.1 U16.43(FANCTL2/ADDR1)
NC_P3V3_STBY_CLK: PU3.4(CLK)
NC_P3V3_STBY_ENLDO: PU3.12(ENCLK)
PMBUS_ALERT_N: R674.2 R696.2 R718.2 ; also on sheet 44
PMBUS_HSC_1_ALERT_N: R671.1 R674.1 U13.15(SMBA_N)
PMBUS_HSC_1_CLK_R: R670.1 R673.1 U13.14(SCL)
PMBUS_HSC_1_DAT_R: R669.1 R672.1 U13.13(SDA)
PMBUS_HSC_2_ALERT_N: R693.1 R696.1 U14.15(SMBA_N)
PMBUS_HSC_2_CLK_R: R692.1 R695.1 U14.14(SCL)
PMBUS_HSC_2_DAT_R: R691.1 R694.1 U14.13(SDA)
PMBUS_HSC_3_ALERT_N: R715.1 R718.1 U15.15(SMBA_N)
PMBUS_HSC_3_CLK_R: R714.1 R717.1 U15.14(SCL)
PMBUS_HSC_3_DAT_R: R713.1 R716.1 U15.13(SDA)
PMBUS_HSC_BUF_CLK: R673.2 R695.2 R717.2 ; also on sheet 44
PMBUS_HSC_BUF_DAT: R672.2 R694.2 R716.2 ; also on sheet 44
PU_HWMON_OVT_N: R754.1 U16.36(OVT#)
PU_HWMON_PWRBTN_N: R751.1 U16.38(PWRBTN#/PROCHOT1#)
PU_HWMON_SYSRSTIN_N: R1221.1 U16.31(SYSRSTIN#/FANIN13/PROCHOT3#)
PU_HWMON_WDTRST_N: R752.1 U16.39(WDTRST#/PROCHOT2#)
PWRGD_P3V3: PR13.2 PU4.8(PGOOD) ; also on sheet 41 60 61
PWRGD_P5V: PJ14.2 PR4.2 PU2.16(PGOOD)
PWRGD_P5V_STBY: PR260.2 PU1.16(PGOOD) PU3.11(EN)
PWRGD_P12V_HSC_1: C929.1 R678.1 R680.2 U13.23(PGD)
PWRGD_P12V_HSC_2: C949.1 R700.1 R704.2 U14.23(PGD)
PWRGD_P12V_HSC_3: C969.1 R722.1 R726.2 R1171.1 U15.23(PGD)
RST_BUF_N: R827.2 R1153.2 R1177.2 U22.1(IN) U22.3(IN) U22.5(IN) U22.9(IN) U22.11(IN) U22.13(IN) U23.5(IN) U23.9(IN) U23.11(IN) U23.13(IN) U99.1(IN) U99.3(IN) U99.5(IN) U99.9(IN) U99.11(IN) U99.13(IN) U103.1(IN) U103.3(IN) U103.5(IN) U103.9(IN) U103.11(IN) U103.13(IN) U106.7(1Y)
RST_IPASSHD_A_N: R825.2 U106.1(1A) ; also on sheet 29
RST_IPASSHD_B_N: R826.2 U106.2(1B) ; also on sheet 30
RST_MUX1_N: R1207.2 ; also on sheet 45
RST_MUX1_N_R: R828.2 R1207.1 U99.6(OUT)
RST_MUX2_N: R1208.2 ; also on sheet 45
RST_MUX2_N_R: R829.2 R1208.1 U99.8(OUT)
RST_MUX3_N: R1209.2 ; also on sheet 45
RST_MUX3_N_R: R1152.2 R1209.1 U99.10(OUT)
RST_NIC1_N: U103.2(OUT) ; also on sheet 39
RST_NIC2_N: U103.4(OUT) ; also on sheet 39
RST_NIC3_N: U103.6(OUT) ; also on sheet 40
RST_NIC4_N: U103.8(OUT) ; also on sheet 40
RST_PCIE_SLOT_0_N: U23.6(OUT) ; also on sheet 31
RST_PCIE_SLOT_1_N: U23.8(OUT) ; also on sheet 32
RST_PCIE_SLOT_2_N: U23.10(OUT) ; also on sheet 33
RST_PCIE_SLOT_3_N: U23.12(OUT) ; also on sheet 34
RST_PCIE_SLOT_4_N: U22.2(OUT) ; also on sheet 35
RST_PCIE_SLOT_5_N: U22.4(OUT) ; also on sheet 36
RST_PCIE_SLOT_6_N: U22.6(OUT) ; also on sheet 37
RST_PCIE_SLOT_7_N: U22.8(OUT) ; also on sheet 38
RST_PLX2_N: R1206.2 ; also on sheet 21
RST_PLX2_N_R: R1206.1 U99.4(OUT)
RST_PLX_N: R1178.2 ; also on sheet 9
RST_PLX_N_R: R1178.1 U99.2(OUT)
SH_P3V3_EN: PJ14.1 PU4.4(EN/FF1) PU4.6(EN/FF2)
SH_P3V3_VSEN1+_R: PJ1.1 PR23.2
SMB_HWMON_SCL: R753.1 ; also on sheet 45
SMB_HWMON_SCL_R: R753.2 R759.1 U16.33(SCL)
SMB_HWMON_SDA: R755.1 ; also on sheet 45
SMB_HWMON_SDA_R: R755.2 R760.1 U16.34(SDA)
SW_P3V3_BT1: PC42.1 PU4.25(BOOT1)
SW_P3V3_BT2: PC50.1 PU4.17(BOOT2)
SW_P3V3_FLT: PC37.1 PC38.1 PC39.1 PC46.1 PC52.1 PC53.1 PL5.1 PQ14.D1(3,4) PQ15.D1(3,4)
SW_P3V3_LG1: PQ14.8(G2) PU4.22(LGATE1)
SW_P3V3_LG2: PQ15.8(G2) PU4.20(LGATE2)
SW_P3V3_PH1: PC42.2 PQ14.2(S1) PU4.23(PHASE1)
SW_P3V3_PH2: PC50.2 PQ15.2(S1) PU4.19(PHASE2)
SW_P3V3_STBY_PH: PC28.2 PL4.1 PU3.7(SW)
SW_P3V3_SW1: PL6.1 PQ14.5(S1/D2-1) PQ14.6(S1/D2-2) PQ14.7(S1/D2-3) PR14.2
SW_P3V3_SW2: PL7.1 PQ15.5(S1/D2-1) PQ15.6(S1/D2-2) PQ15.7(S1/D2-3) PR19.2
SW_P3V3_UG1: PQ14.1(G1) PU4.24(UGATE1)
SW_P3V3_UG2: PQ15.1(G1) PU4.18(UGATE2)
SW_P5V_BT: PC22.1 PU2.14(VBST)
SW_P5V_FILT: PC13.1 PC14.1 PC15.1 PC18.1 PL2.1 PQ13.D1(3,4)
SW_P5V_LG: PQ13.8(G2) PU2.11(DRVL)
SW_P5V_PH: PL3.1 PQ13.5(S1/D2-1) PQ13.6(S1/D2-2) PQ13.7(S1/D2-3)
SW_P5V_STBY_BT: PC1448.1 PU1.14(VBST)
SW_P5V_STBY_FILT: PC1447.1 PC1452.1 PC1453.1 PC1457.1 PL23.1 PQ20.D1(3,4)
SW_P5V_STBY_LG: PQ20.8(G2) PU1.11(DRVL)
SW_P5V_STBY_PH: PL22.1 PQ20.5(S1/D2-1) PQ20.6(S1/D2-2) PQ20.7(S1/D2-3)
SW_P5V_STBY_SW: PC1448.2 PQ20.2(S1) PU1.12(SW)
SW_P5V_STBY_UG: PQ20.1(G1) PU1.13(DRVH)
SW_P5V_SW: PC22.2 PQ13.2(S1) PU2.12(SW)
SW_P5V_UG: PQ13.1(G1) PU2.13(DRVH)
SYS_FAN_A_LED: Q36.2(G1) R791.1 U16.61(VOLT_FAULT#/PVID4/GPIO5)
SYS_FAN_A_LED_N: J22.B12(RSVD) Q36.6(D1)
SYS_FAN_A_PRSNT_N: J22.B17(PRSNT2_N) R784.1 U16.57(FANIN9/PVID0/GPIO1)
SYS_FAN_A_PWM_0_1: J22.B5(SMCLK) J22.B8(3.3V_~{0}) R800.1 U16.51(FANCTL6)
SYS_FAN_A_TACH_0: J22.B15(PETn0) R787.1 U16.40(FANIN1)
SYS_FAN_A_TACH_1: J22.B14(PETp0) R789.1 U16.42(FANIN2)
SYS_FAN_B_LED: Q36.5(G2) R793.1 U16.62(FAN_FAULT#PVID5/GPIO6)
SYS_FAN_B_LED_N: J24.B12(RSVD) Q36.3(D2)
SYS_FAN_B_PRSNT_N: J24.B17(PRSNT2_N) R785.1 U16.58(FANIN10/PVID1/GPIO2)
SYS_FAN_B_PWM_2_3: J24.B5(SMCLK) J24.B8(3.3V_~{0}) R801.1 U16.45(FANCTL3)
SYS_FAN_B_TACH_2: J24.B15(PETn0) R790.1 U16.44(FANIN3)
SYS_FAN_B_TACH_3: J24.B14(PETp0) R792.1 U16.46(FANIN4)
SYS_FAN_C_LED: Q37.2(G1) R795.1 U16.63(OVT2#/SCL_SVI/PVID6/GPIO7)
SYS_FAN_C_LED_N: J23.B12(RSVD) Q37.6(D1)
SYS_FAN_C_PRSNT_N: J23.B17(PRSNT2_N) R786.1 U16.59(FANIN11/PECI_REQ#/PVID2/GPIO3)
SYS_FAN_C_PWM_4_5: J23.B5(SMCLK) J23.B8(3.3V_~{0}) R802.1 U16.47(FANCTL4)
SYS_FAN_C_TACH_4: J23.B15(PETn0) R794.1 U16.48(FANIN5)
SYS_FAN_C_TACH_5: J23.B14(PETp0) R796.1 U16.50(FANIN6)
SYS_FAN_D_LED: Q37.5(G2) R797.1 U16.64(OVT3#/SDA_SVI/PVID7/GPIO8)
SYS_FAN_D_LED_N: J25.B12(RSVD) Q37.3(D2)
SYS_FAN_D_PRSNT_N: J25.B17(PRSNT2_N) R788.1 U16.60(FANIN12/PVID3/GPIO4)
SYS_FAN_D_PWM_6_7: J25.B5(SMCLK) J25.B8(3.3V_~{0}) R803.1 U16.49(FANCTL5)
SYS_FAN_D_TACH_6: J25.B15(PETn0) R798.1 U16.52(FANIN7)
SYS_FAN_D_TACH_7: J25.B14(PETp0) R799.1 U16.54(FANIN8)
TP_HWM_PECI: U16.29(PECI/SCL_TSI)
TP_HWM_THERMTRIP_N: U16.30(SDA_TSI/THERMTRIP#)
TP_HWMON_VTT_IN: U16.28(VTT)
TP_RST_BUF_OD_RESERVE_2: U99.12(OUT)
TP_RST_BUF_RESERVE_1: U22.10(OUT)
TP_RST_BUF_RESERVE_2: U22.12(OUT)
TP_RST_BUF_RESERVE_3: U103.10(OUT)
TP_RST_BUF_RESERVE_4: U103.12(OUT)
TP_RST_BUF_RESERVE_U23A: U23.2(OUT)
TP_RST_BUF_RESERVE_U23B: U23.4(OUT)
TP_RST_ORGATE_RESERVE_U106: U106.3(2Y)
VREF_HWMON: C1000.1 U16.1(VREF)
N17429270: C931.1 R689.1 R861.1
N17430190: PQ3.4 R687.1
N17430195: PQ4.4 R688.1
N30209885: PQ2.4 R686.1
N30210691: PQ1.4 R685.1
N30335962: C951.1 R711.1 R868.1
N30335991: PQ7.4 R709.1
N30335995: PQ8.4 R710.1
N30336094: PQ6.4 R708.1
N30336133: PQ5.4 R707.1
N30338390: C971.1 R733.1 R875.1
N30338419: PQ11.4 R731.1
N30338423: PQ12.4 R732.1
N30338522: PQ10.4 R730.1
N30338561: PQ9.4 R729.1
N31319487: R881.1 U16.12(VDSEN17-/TR4-/D4-)
N31319511: R881.2 U16.11(VDSEN17+/TR4+/D4+)
N31319517: R882.2 U16.9(VDSEN16+/TR3+/D3+)
N31319523: R883.2 U16.7(VDSEN15+/TR2+/D2+)
N31319529: R883.1 U16.8(VDSEN15-/TR2-/D2-)
N31319548: R882.1 U16.10(VDSEN16-/TR3-/D3-)
N32737639: R1170.2 U16.5(VDSEN14+/TR1+/D1+)
N32737645: R1170.1 U16.6(VDSEN14-/TR1-/D1-)

Not connected (* = marked no-connect by the designer): J22 A1(PRSNT1_N) A5(JTAG2) A6(JTAG3) A7(JTAG4) A8(JTAG5) A11(PERST_N) A13(REFCLK+) A14(REFCLK-) A16(PERp0) A17(PERn0) B6(SMDAT) B9(JTAG1) B11(WAKE_N); J23 A1(PRSNT1_N) A5(JTAG2) A6(JTAG3) A7(JTAG4) A8(JTAG5) A11(PERST_N) A13(REFCLK+) A14(REFCLK-) A16(PERp0) A17(PERn0) B6(SMDAT) B9(JTAG1) B11(WAKE_N); J24 A1(PRSNT1_N) A5(JTAG2) A6(JTAG3) A7(JTAG4) A8(JTAG5) A11(PERST_N) A13(REFCLK+) A14(REFCLK-) A16(PERp0) A17(PERn0) B6(SMDAT) B9(JTAG1) B11(WAKE_N); J25 A1(PRSNT1_N) A5(JTAG2) A6(JTAG3) A7(JTAG4) A8(JTAG5) A11(PERST_N) A13(REFCLK+) A14(REFCLK-) A16(PERp0) A17(PERn0) B6(SMDAT) B9(JTAG1) B11(WAKE_N); PU1 15(NC)*; PU2 15(NC)*; PU4 7(CLKOUT/REFIN)*; U13 4(NC1)* 6(NC2)* 21(VAUX)*; U14 4(NC1)* 6(NC2)* 21(VAUX)*; U15 4(NC1)* 6(NC2)* 21(VAUX)*; U16 3(VSEN12/TR5)* 35(SMI#/FANIN14/PROCHOT4#) 37(BEEP)* 53(PROCHOT1#/FANCTL7) 55(PROCHOT2#/FANCTL8)*

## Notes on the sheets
sheet 56
- VFB=0.6V
sheet 57
- VFB=0.6V
- BLANK
sheet 59
- 6*6
- 6*6
- 12m£[
- 12m£[
- 12m£[
- 5x6
- 5x6
- 5x6
- 12m£[
- 12m£[
- 12m£[
- 5x6
- 5x6
- 5x6
